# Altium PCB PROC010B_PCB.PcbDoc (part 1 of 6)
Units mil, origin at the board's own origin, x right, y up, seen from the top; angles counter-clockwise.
Board outline 3180 x 2565 mil, 6 copper layers (TOP, L2, L3, L4, L5, BOTTOM), stack 55.54 mil thick; 362 components, 264 nets, 1248 pads, 1144 vias.
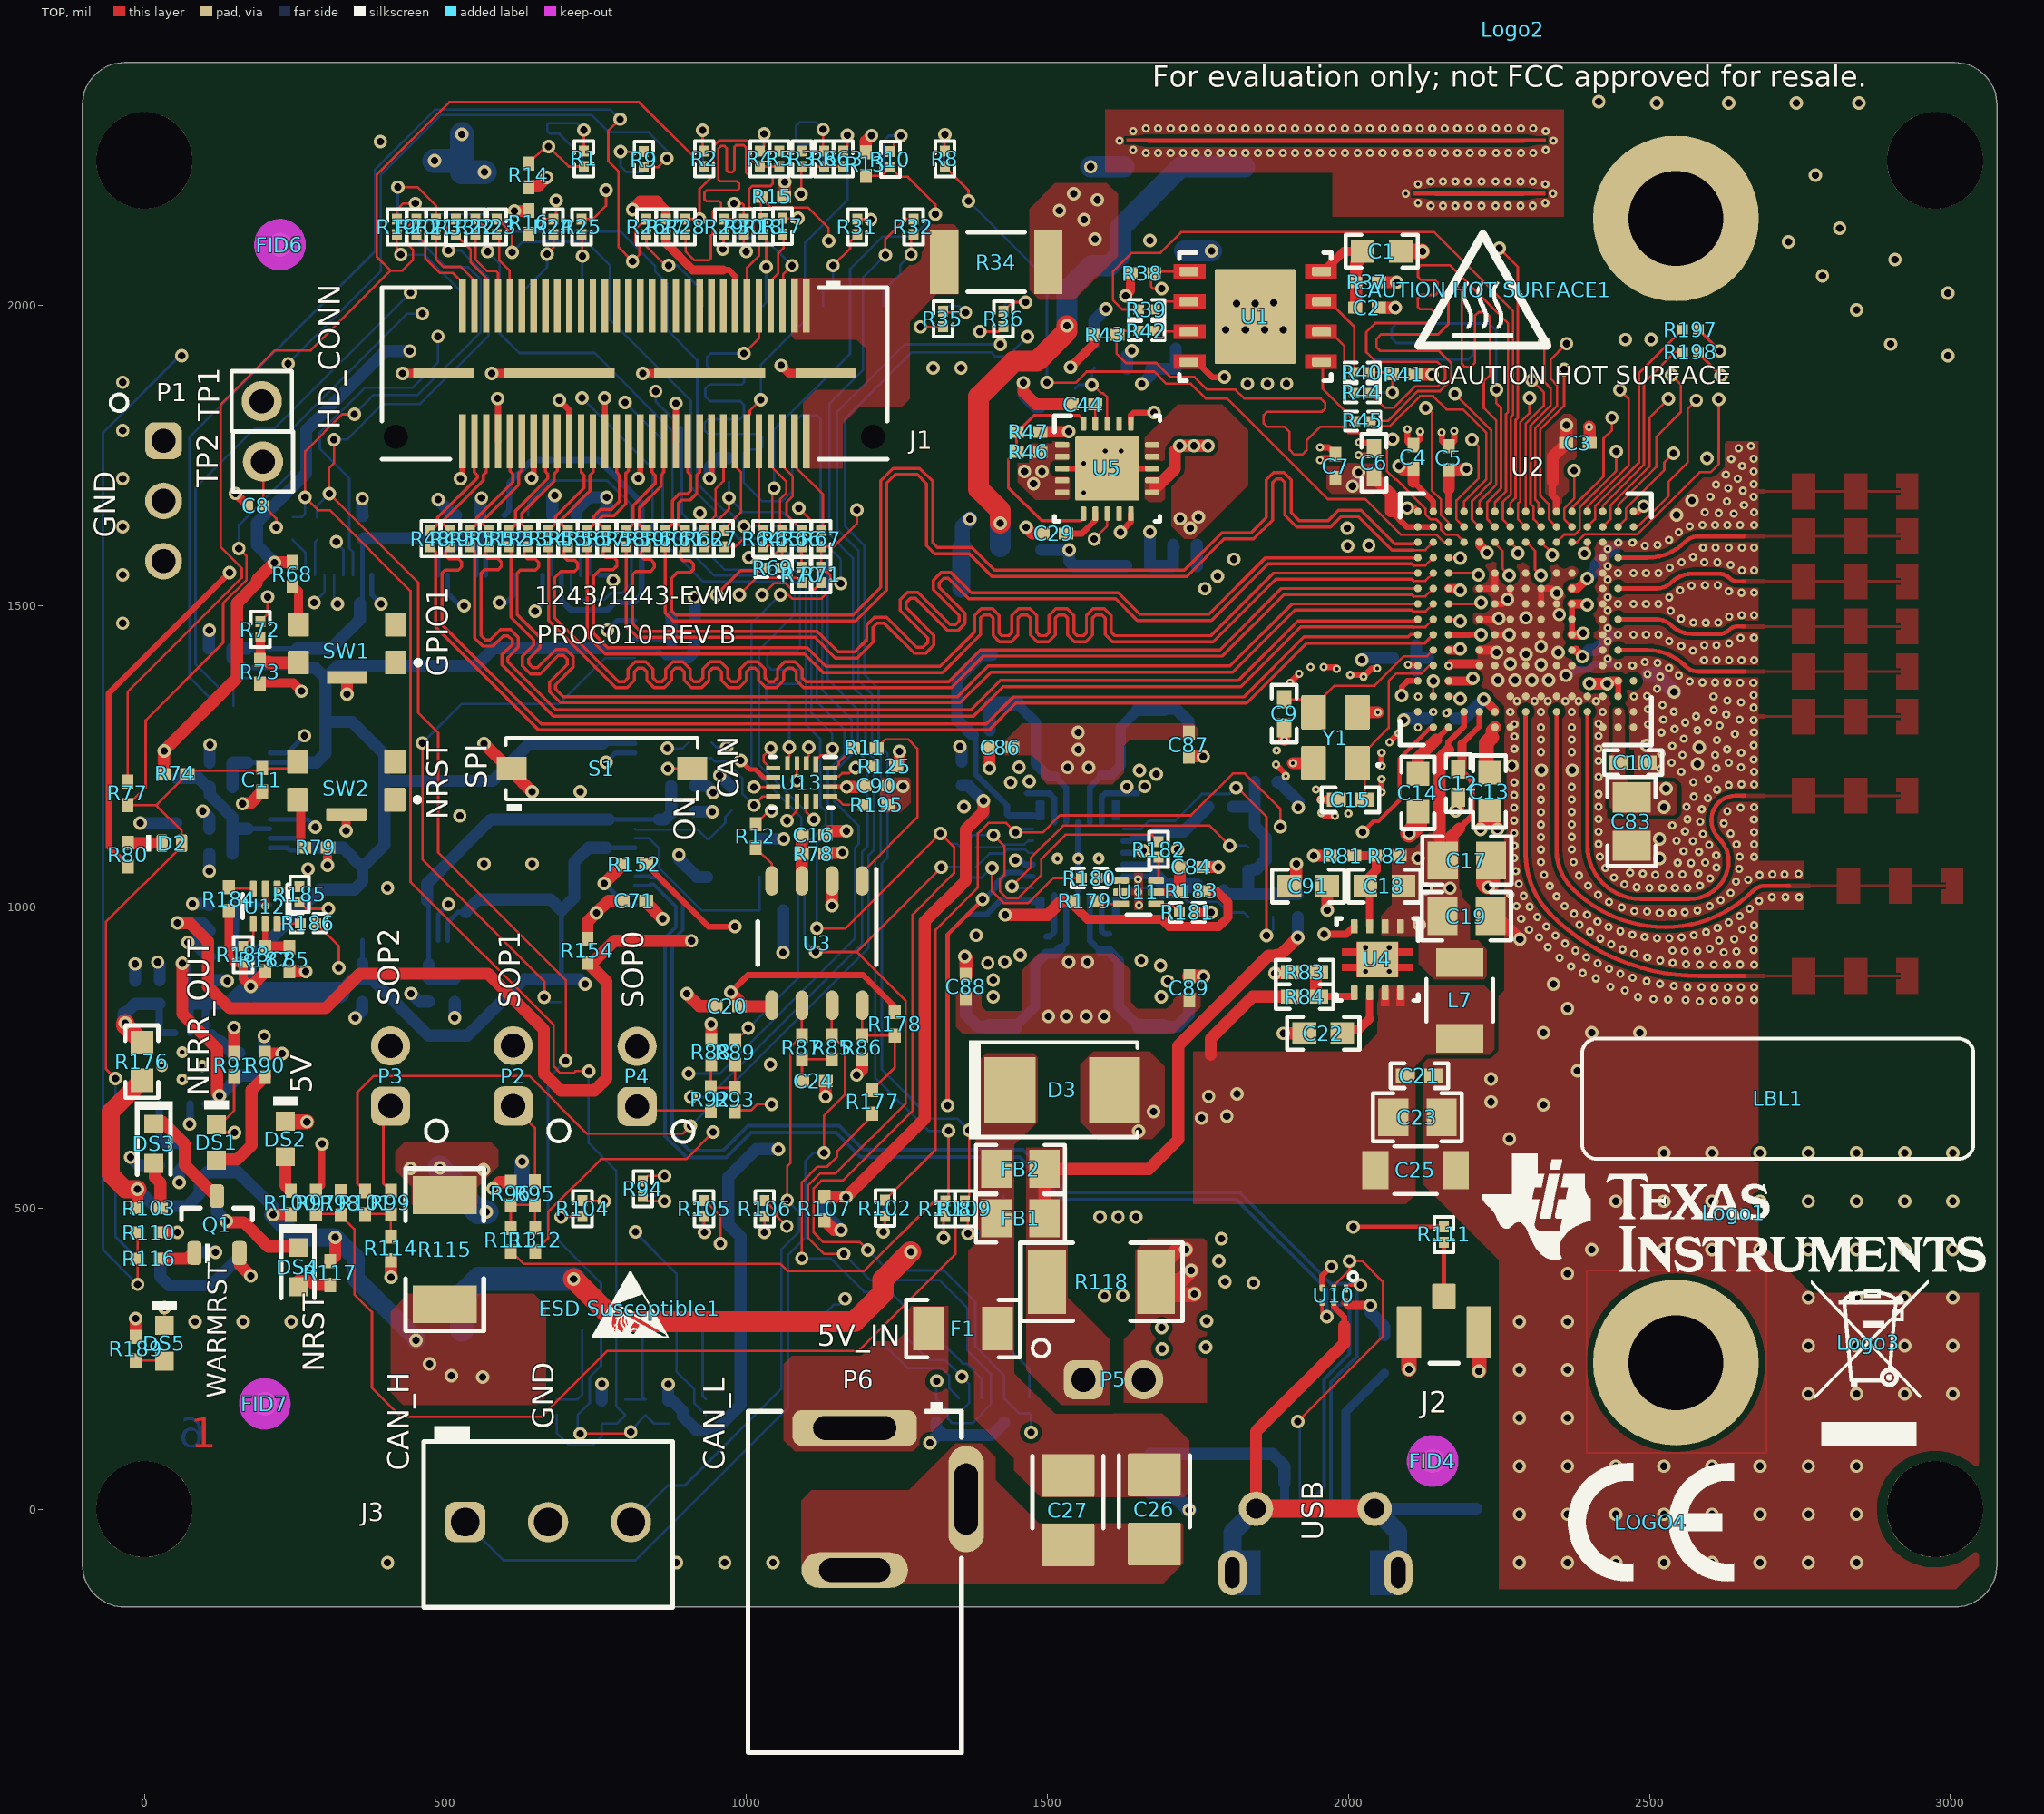
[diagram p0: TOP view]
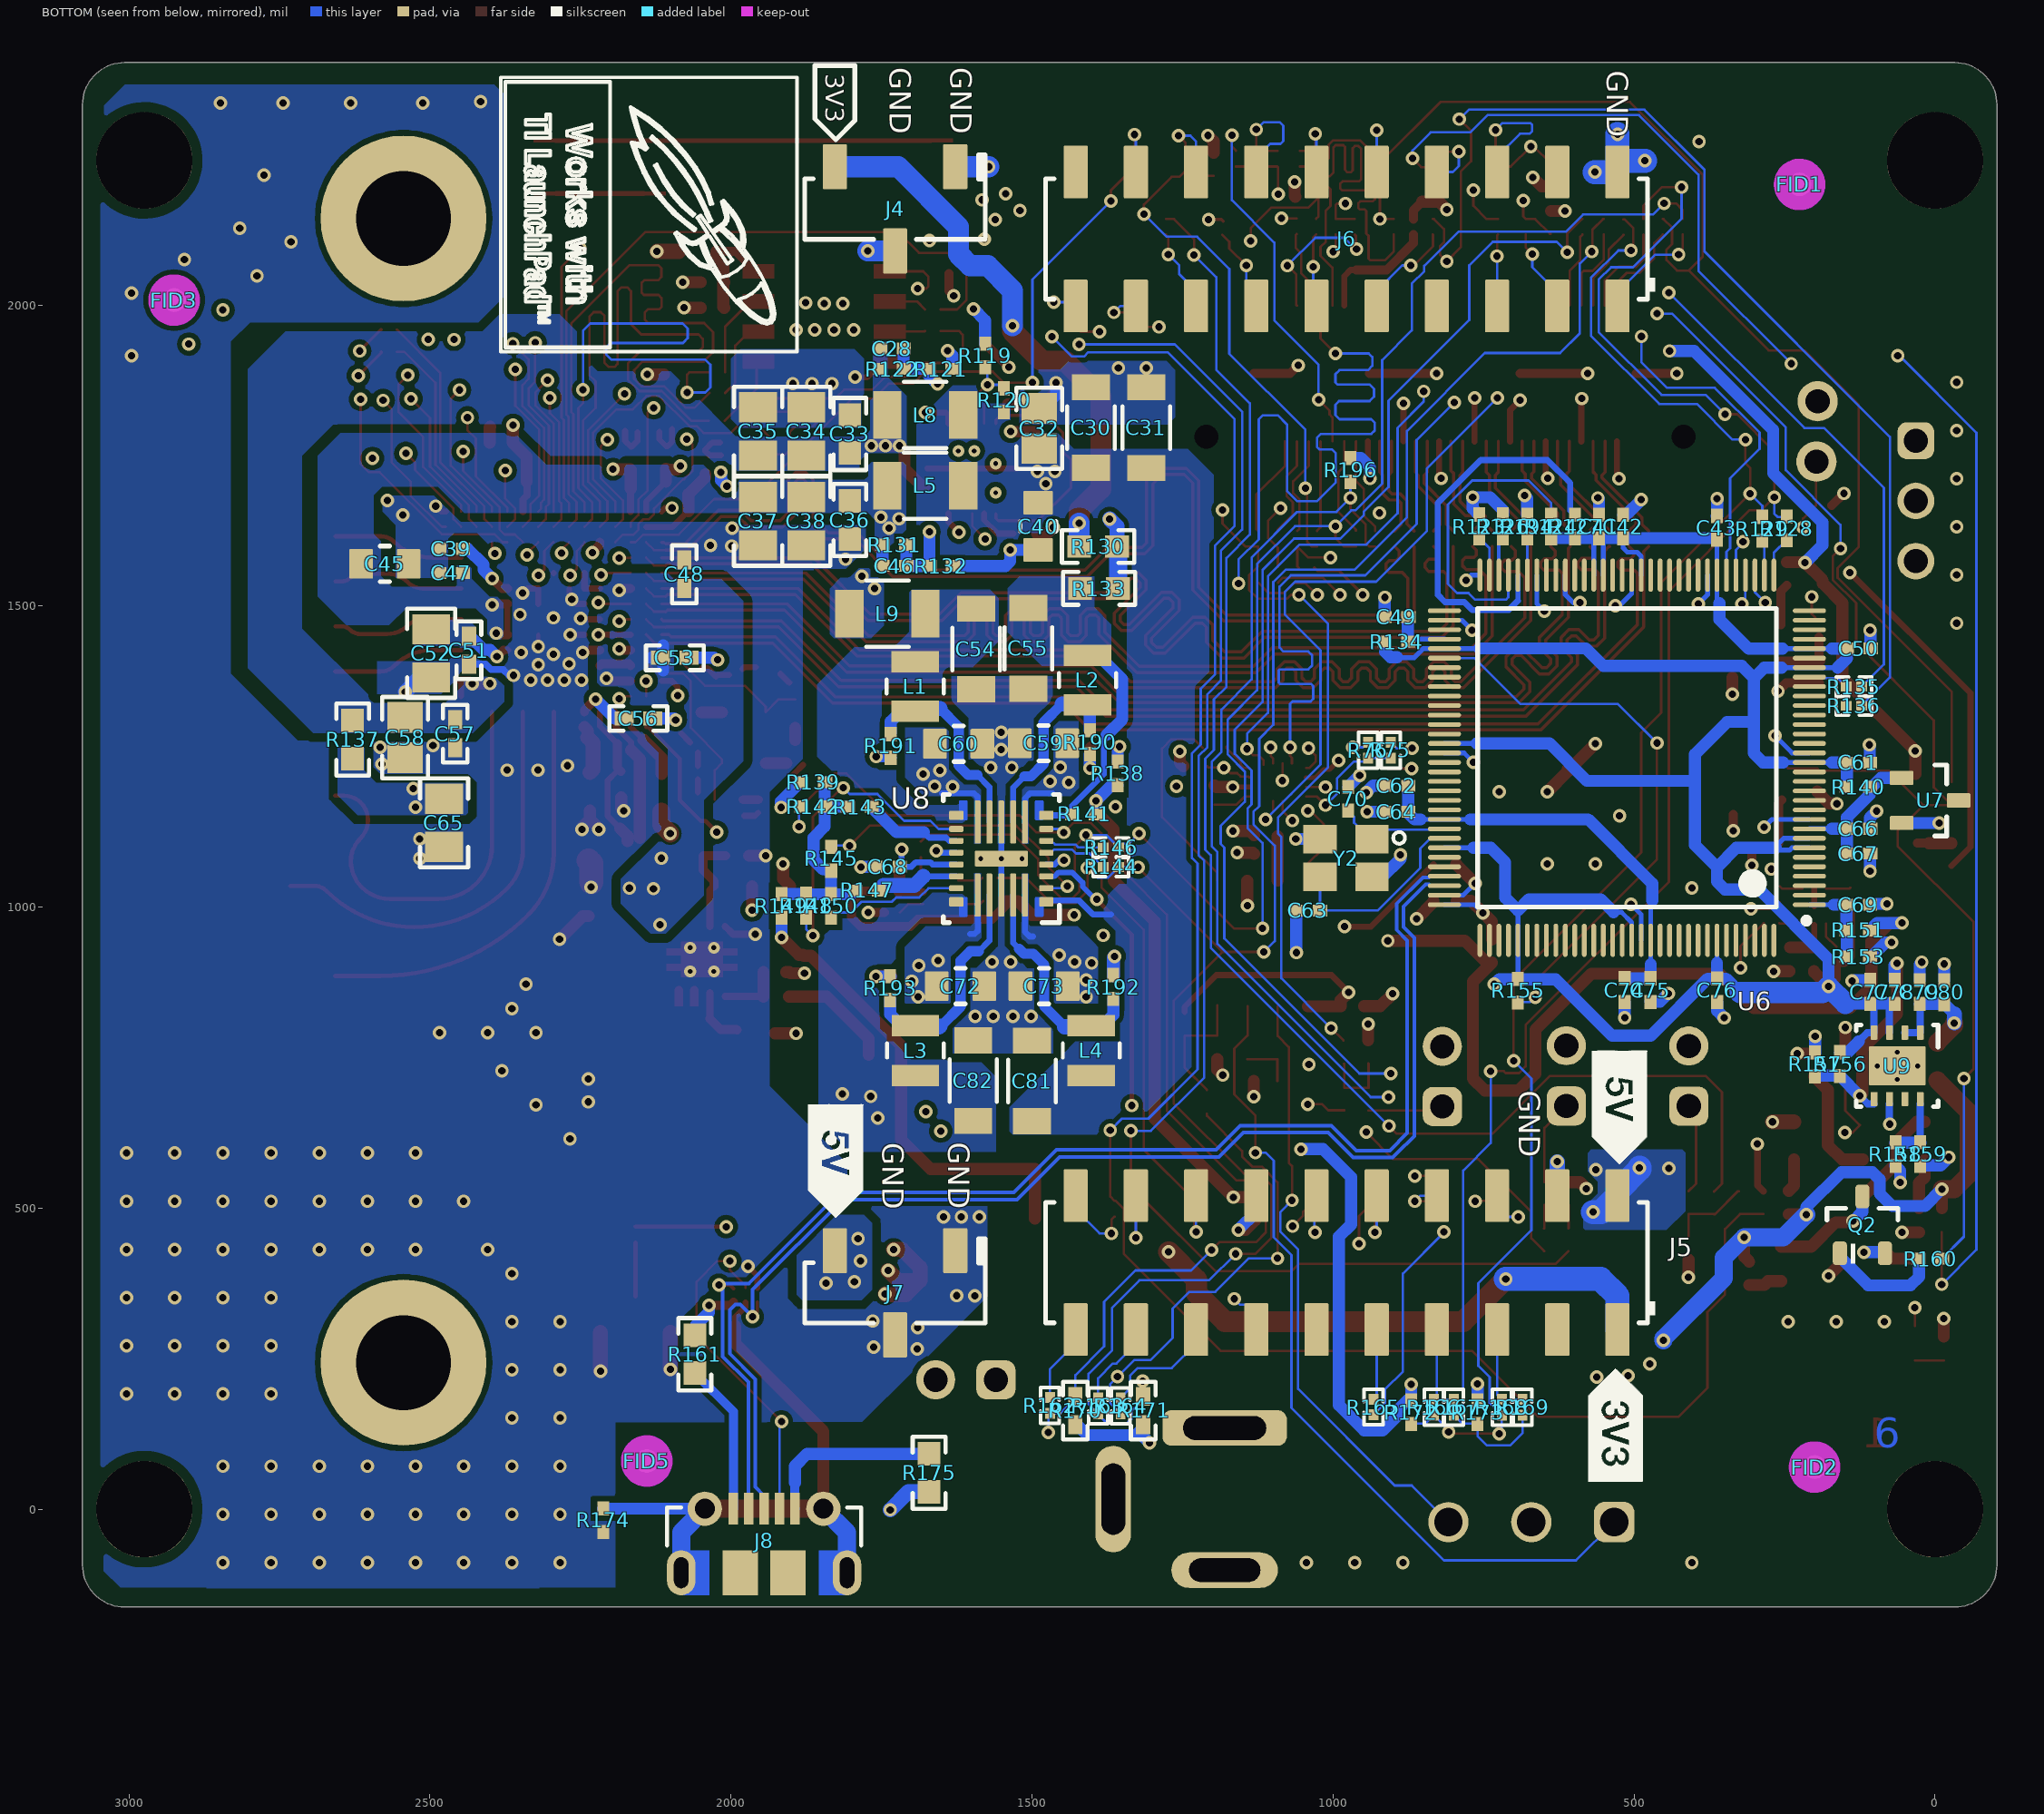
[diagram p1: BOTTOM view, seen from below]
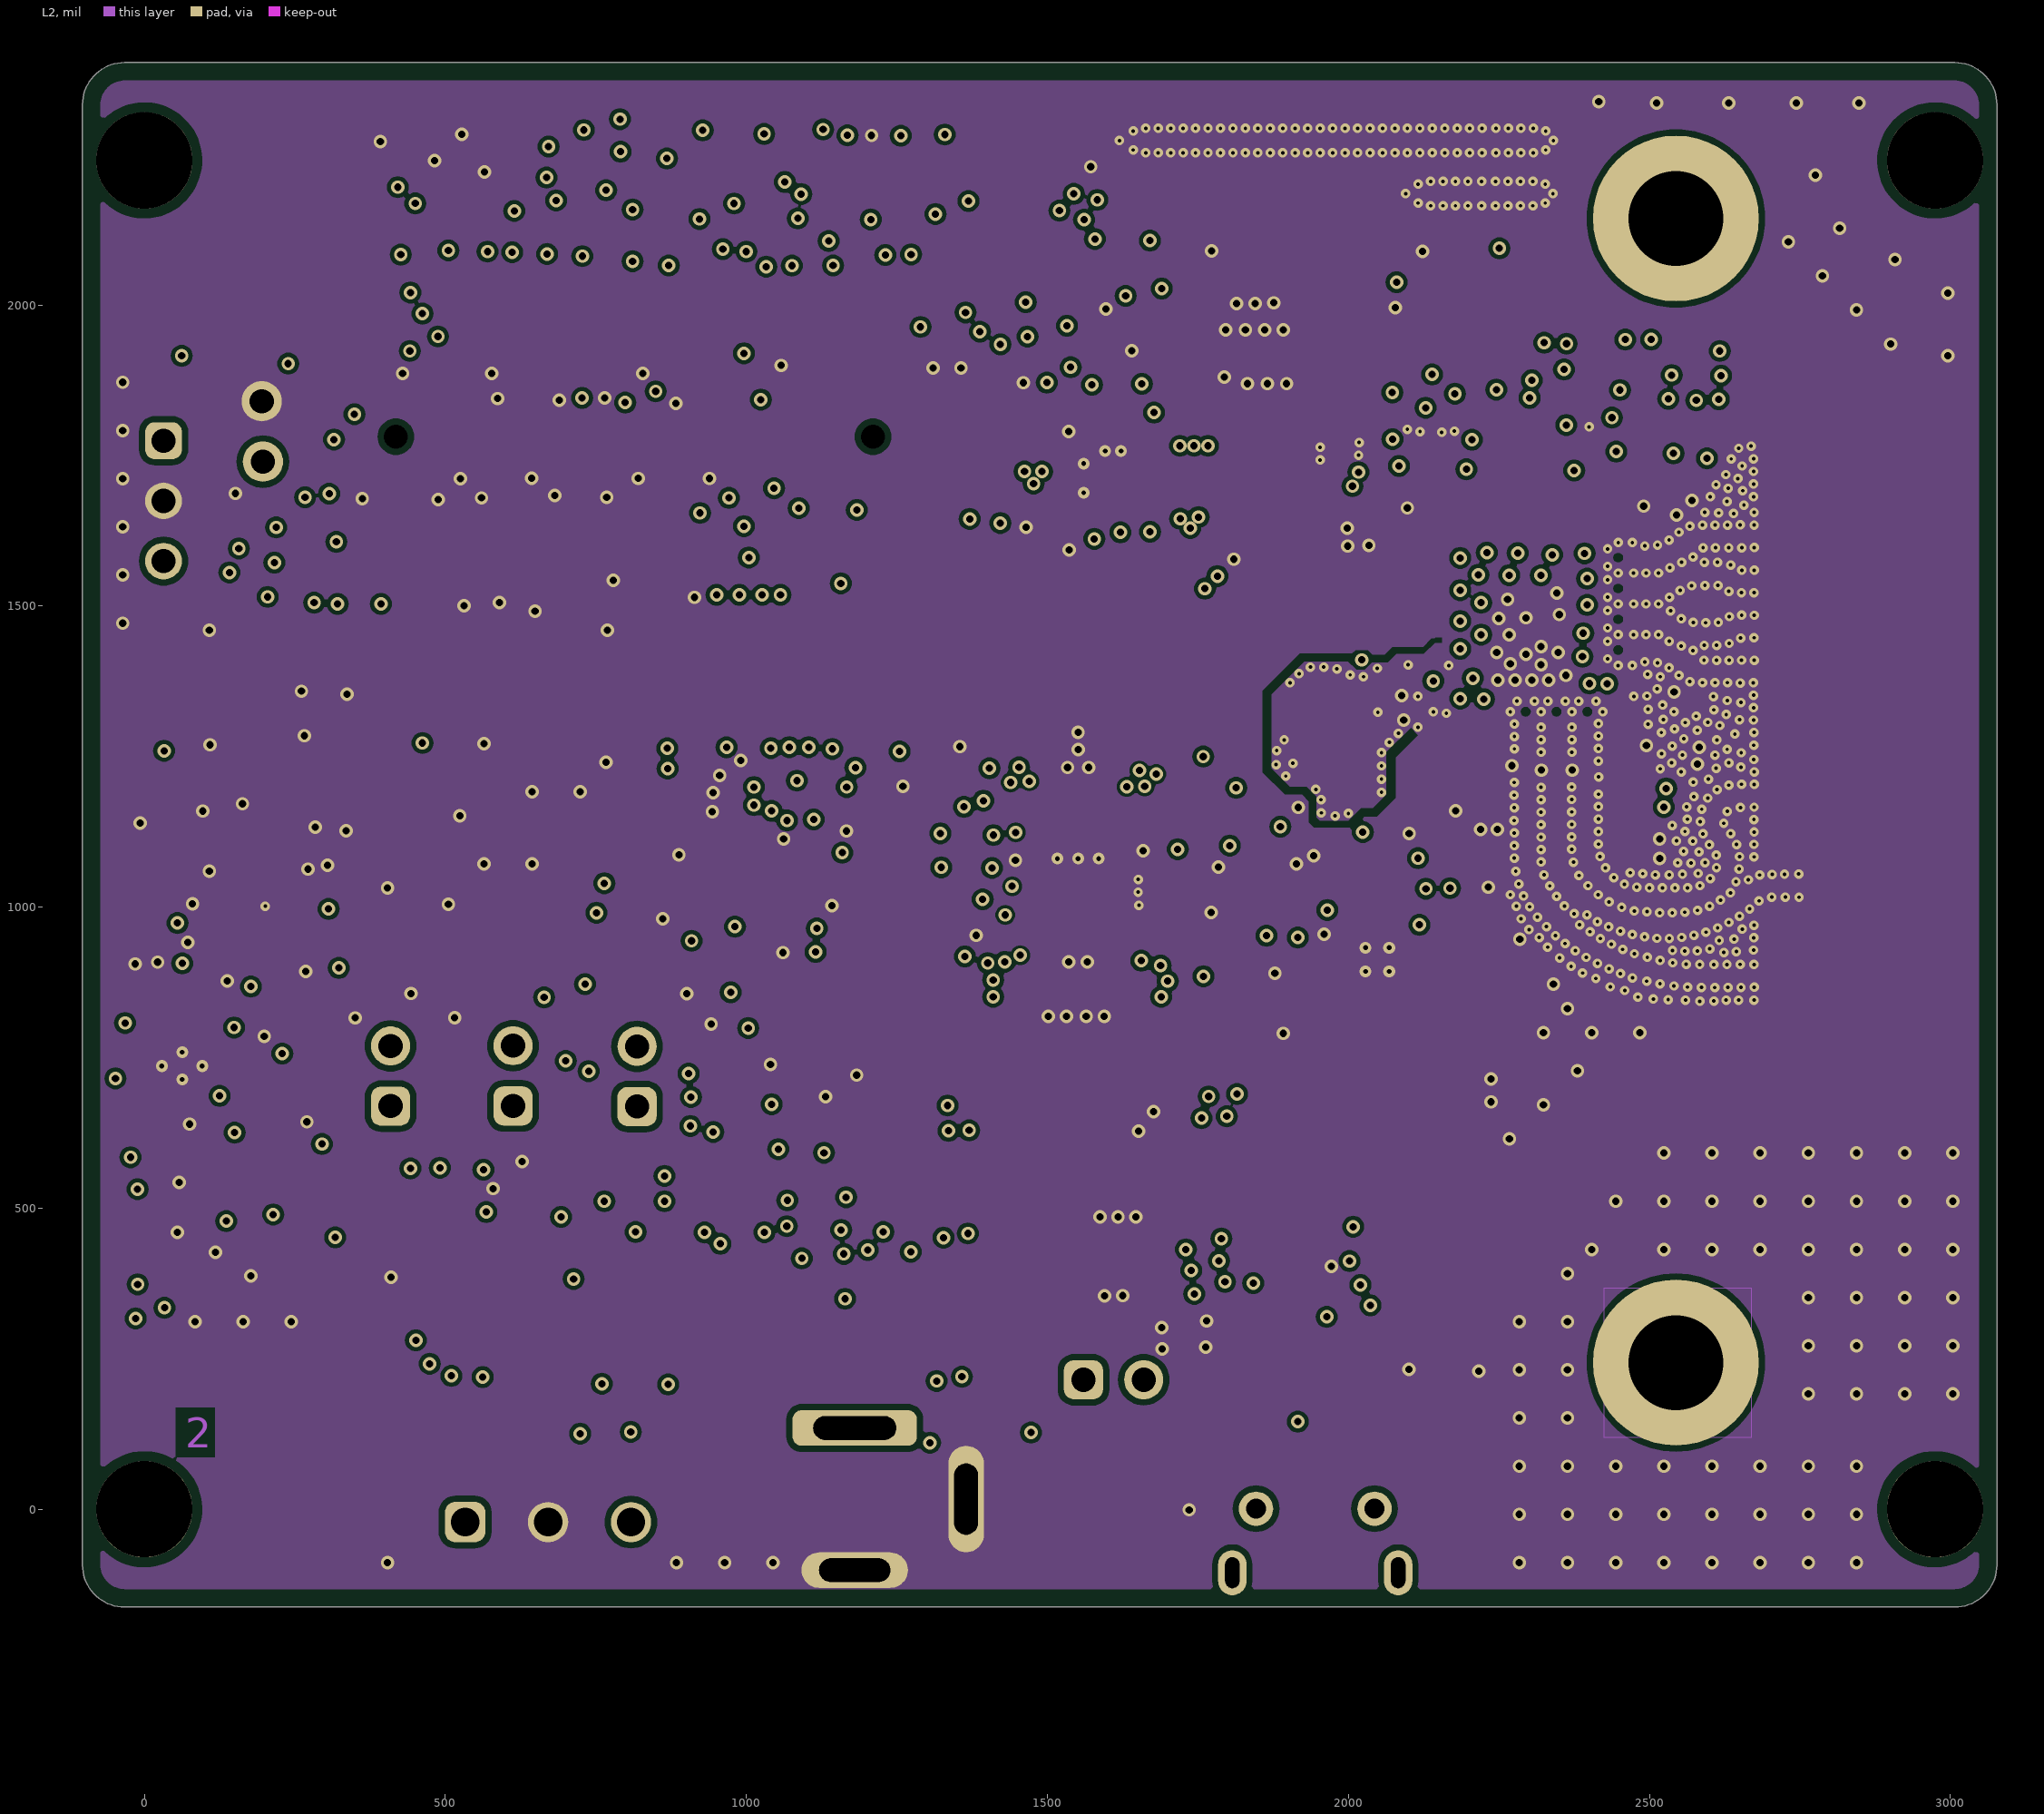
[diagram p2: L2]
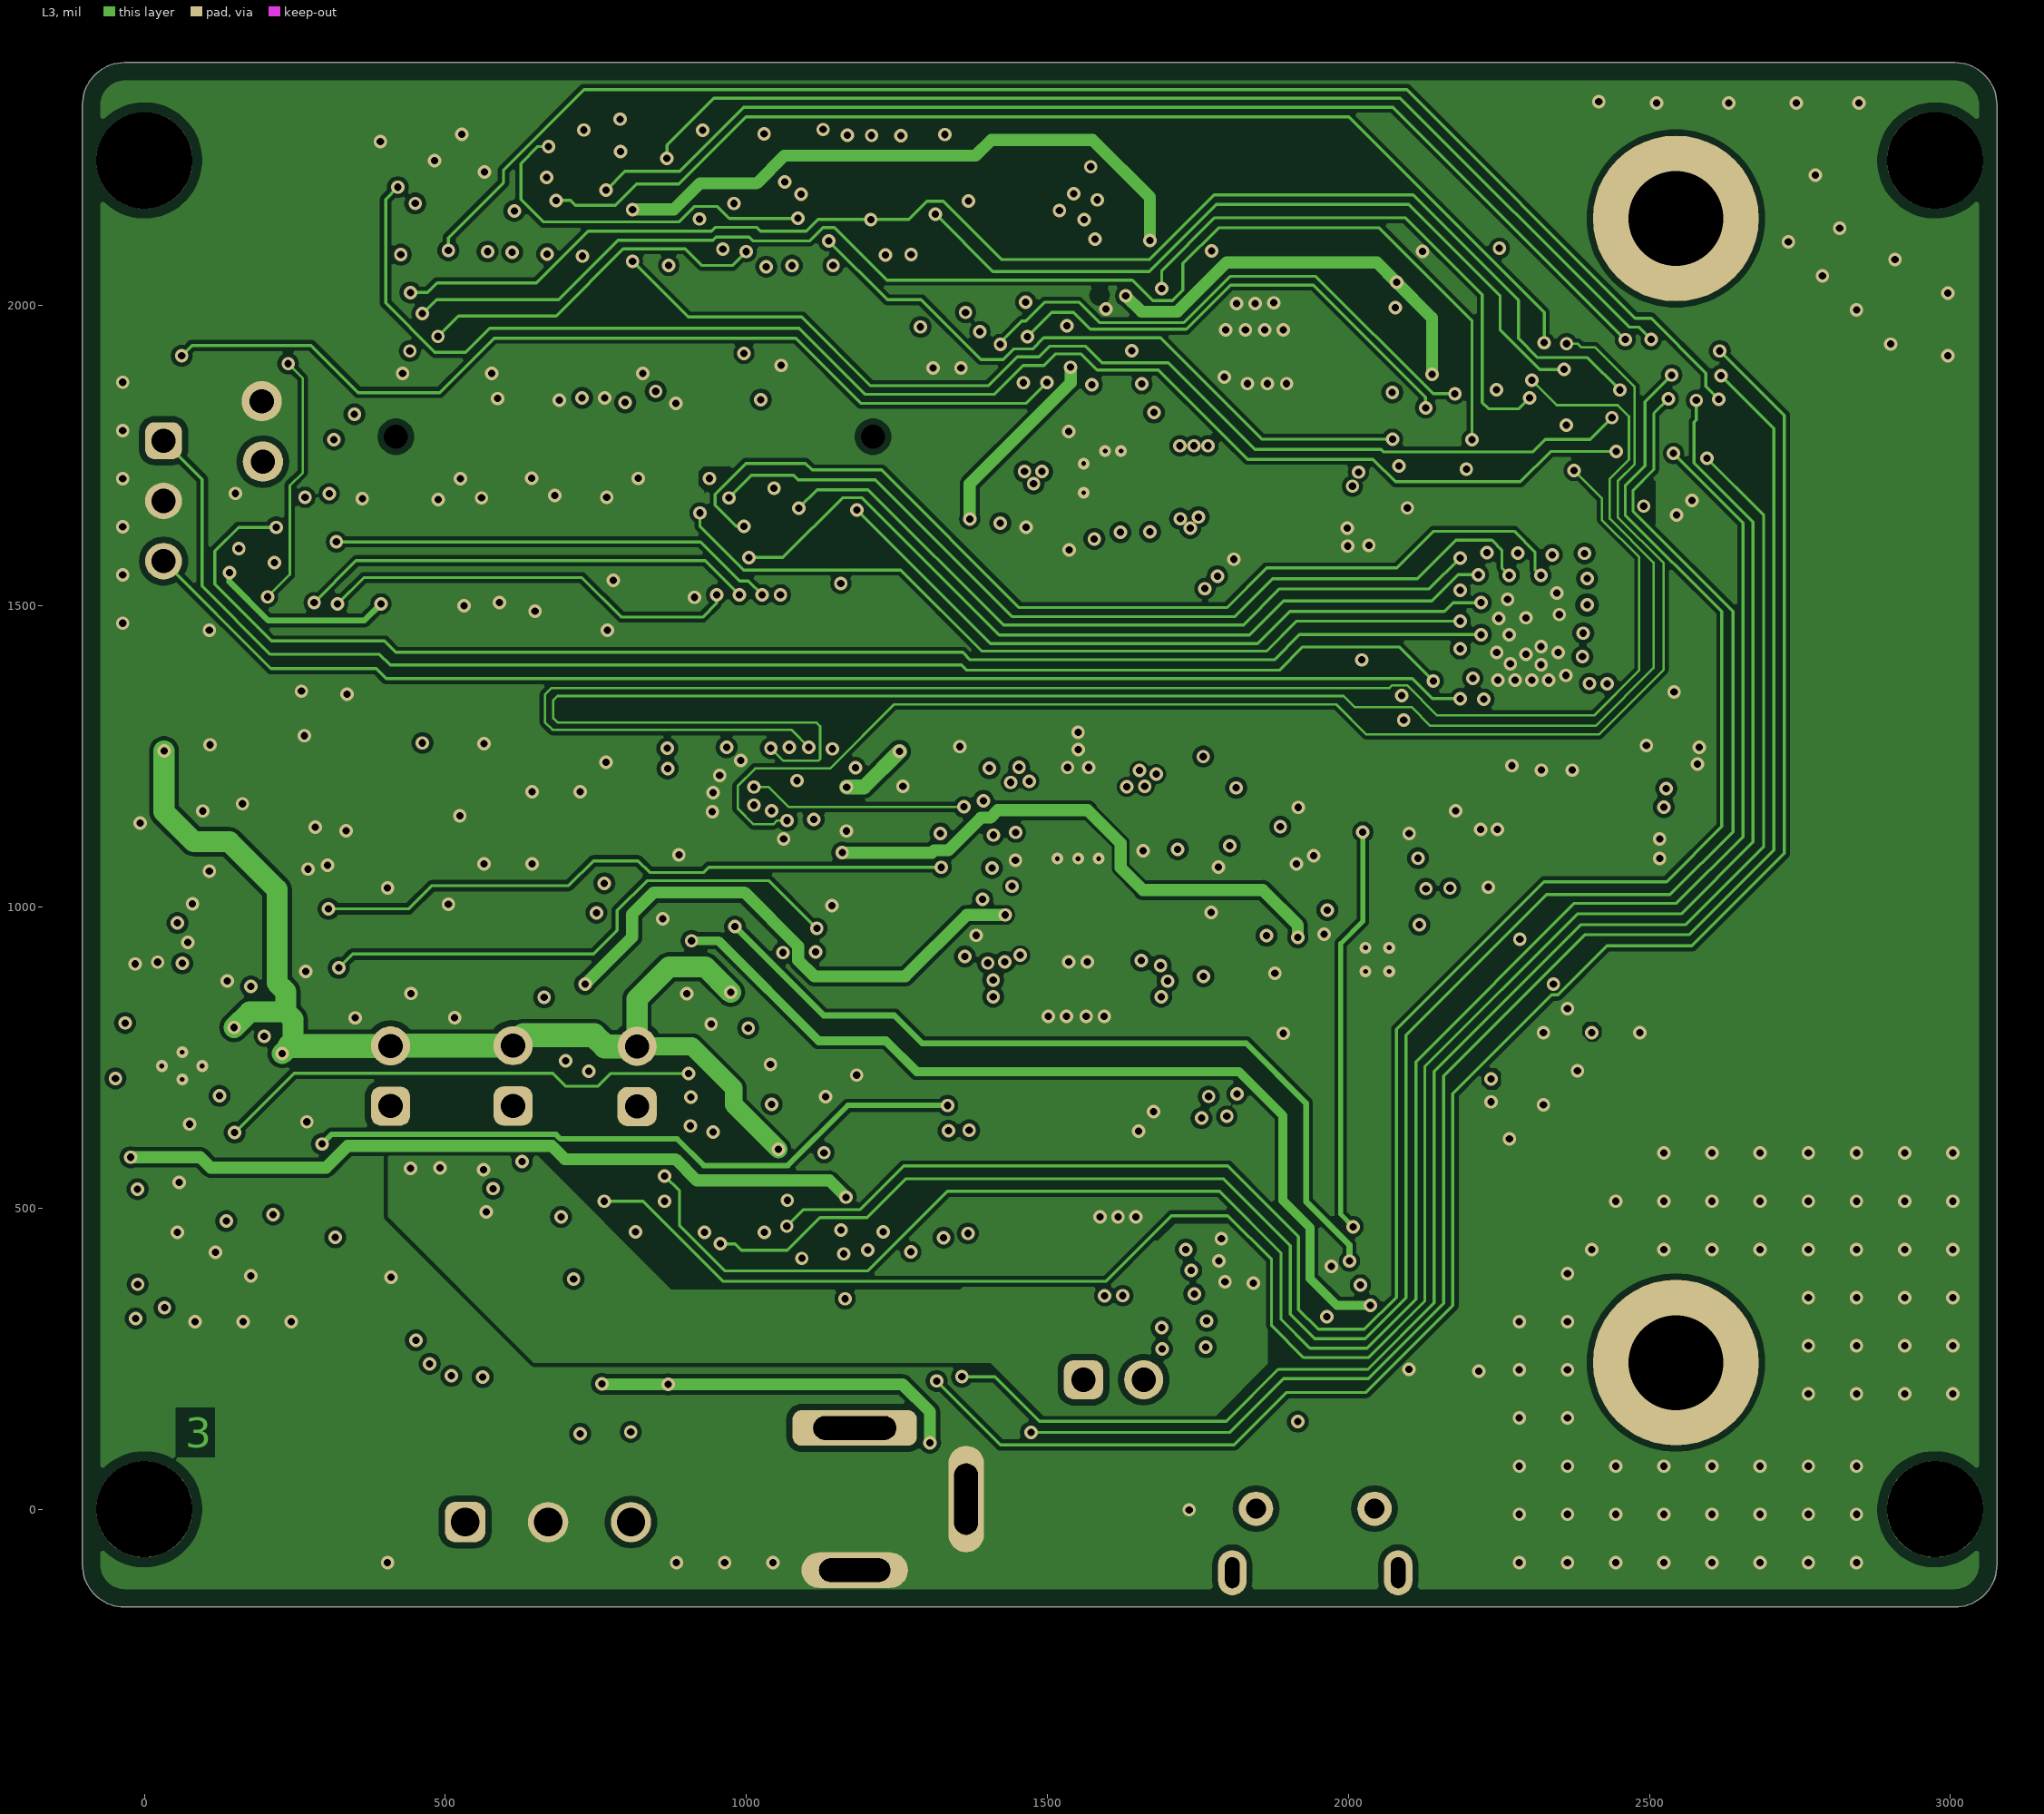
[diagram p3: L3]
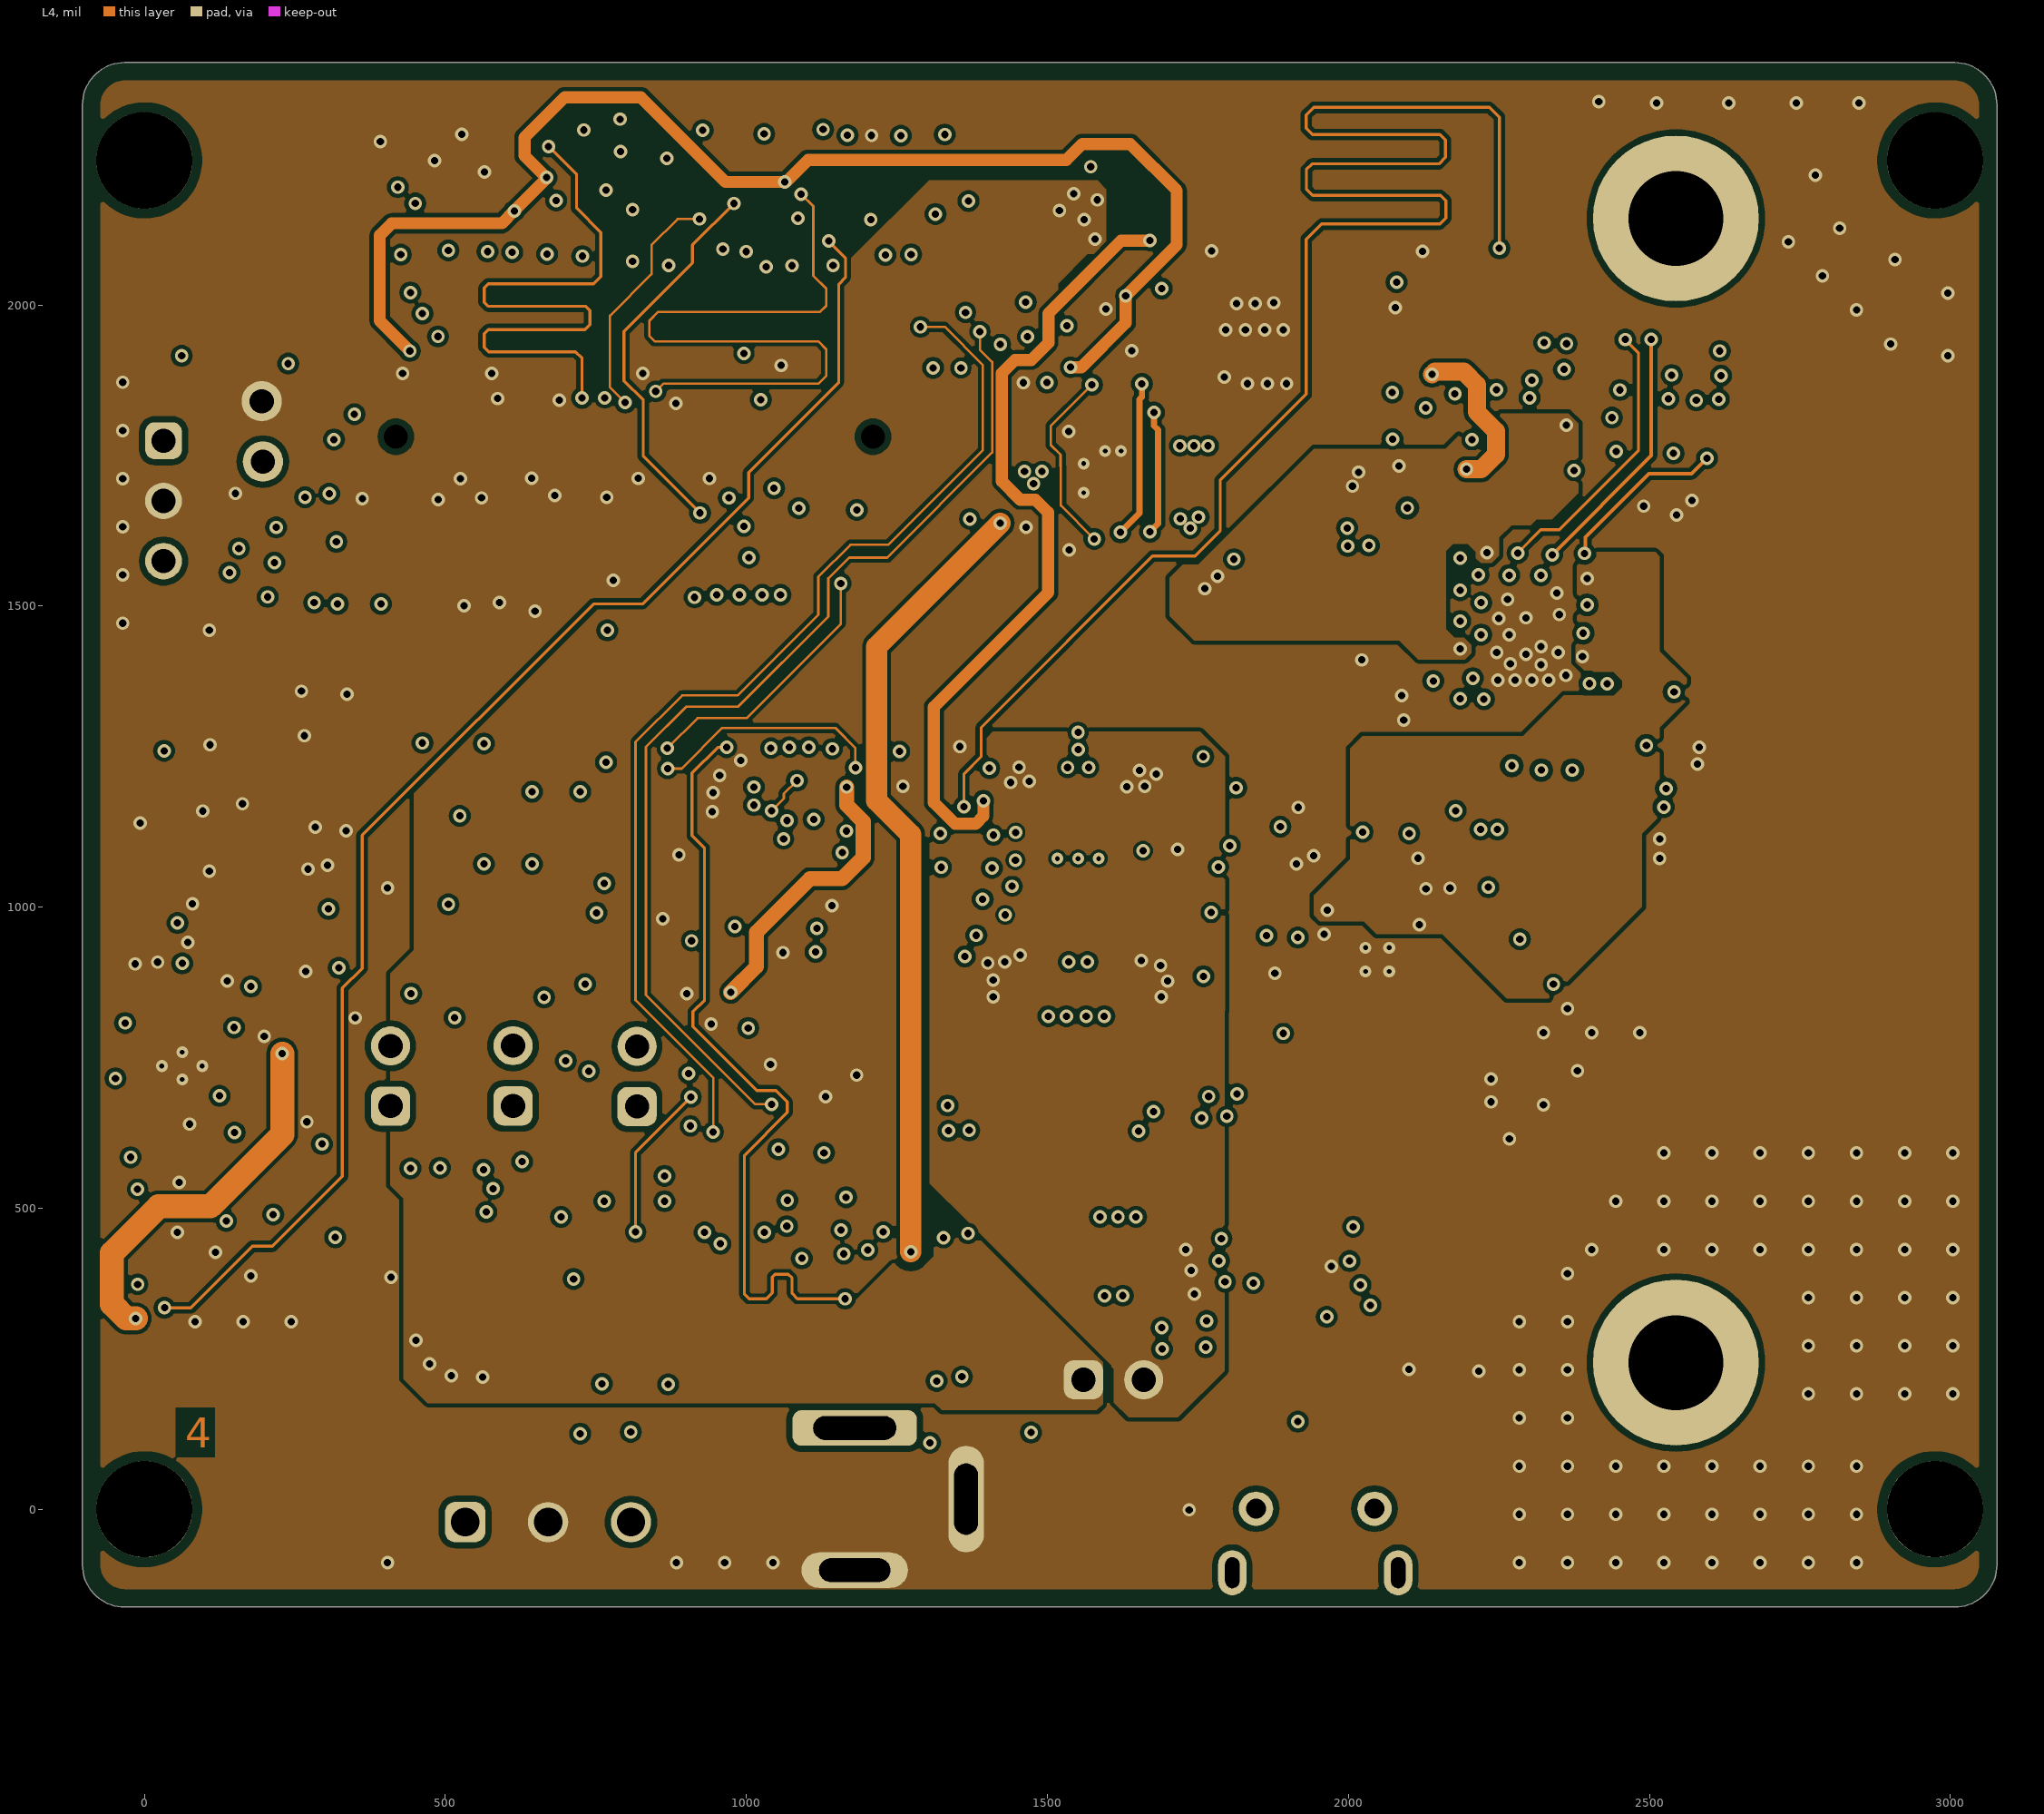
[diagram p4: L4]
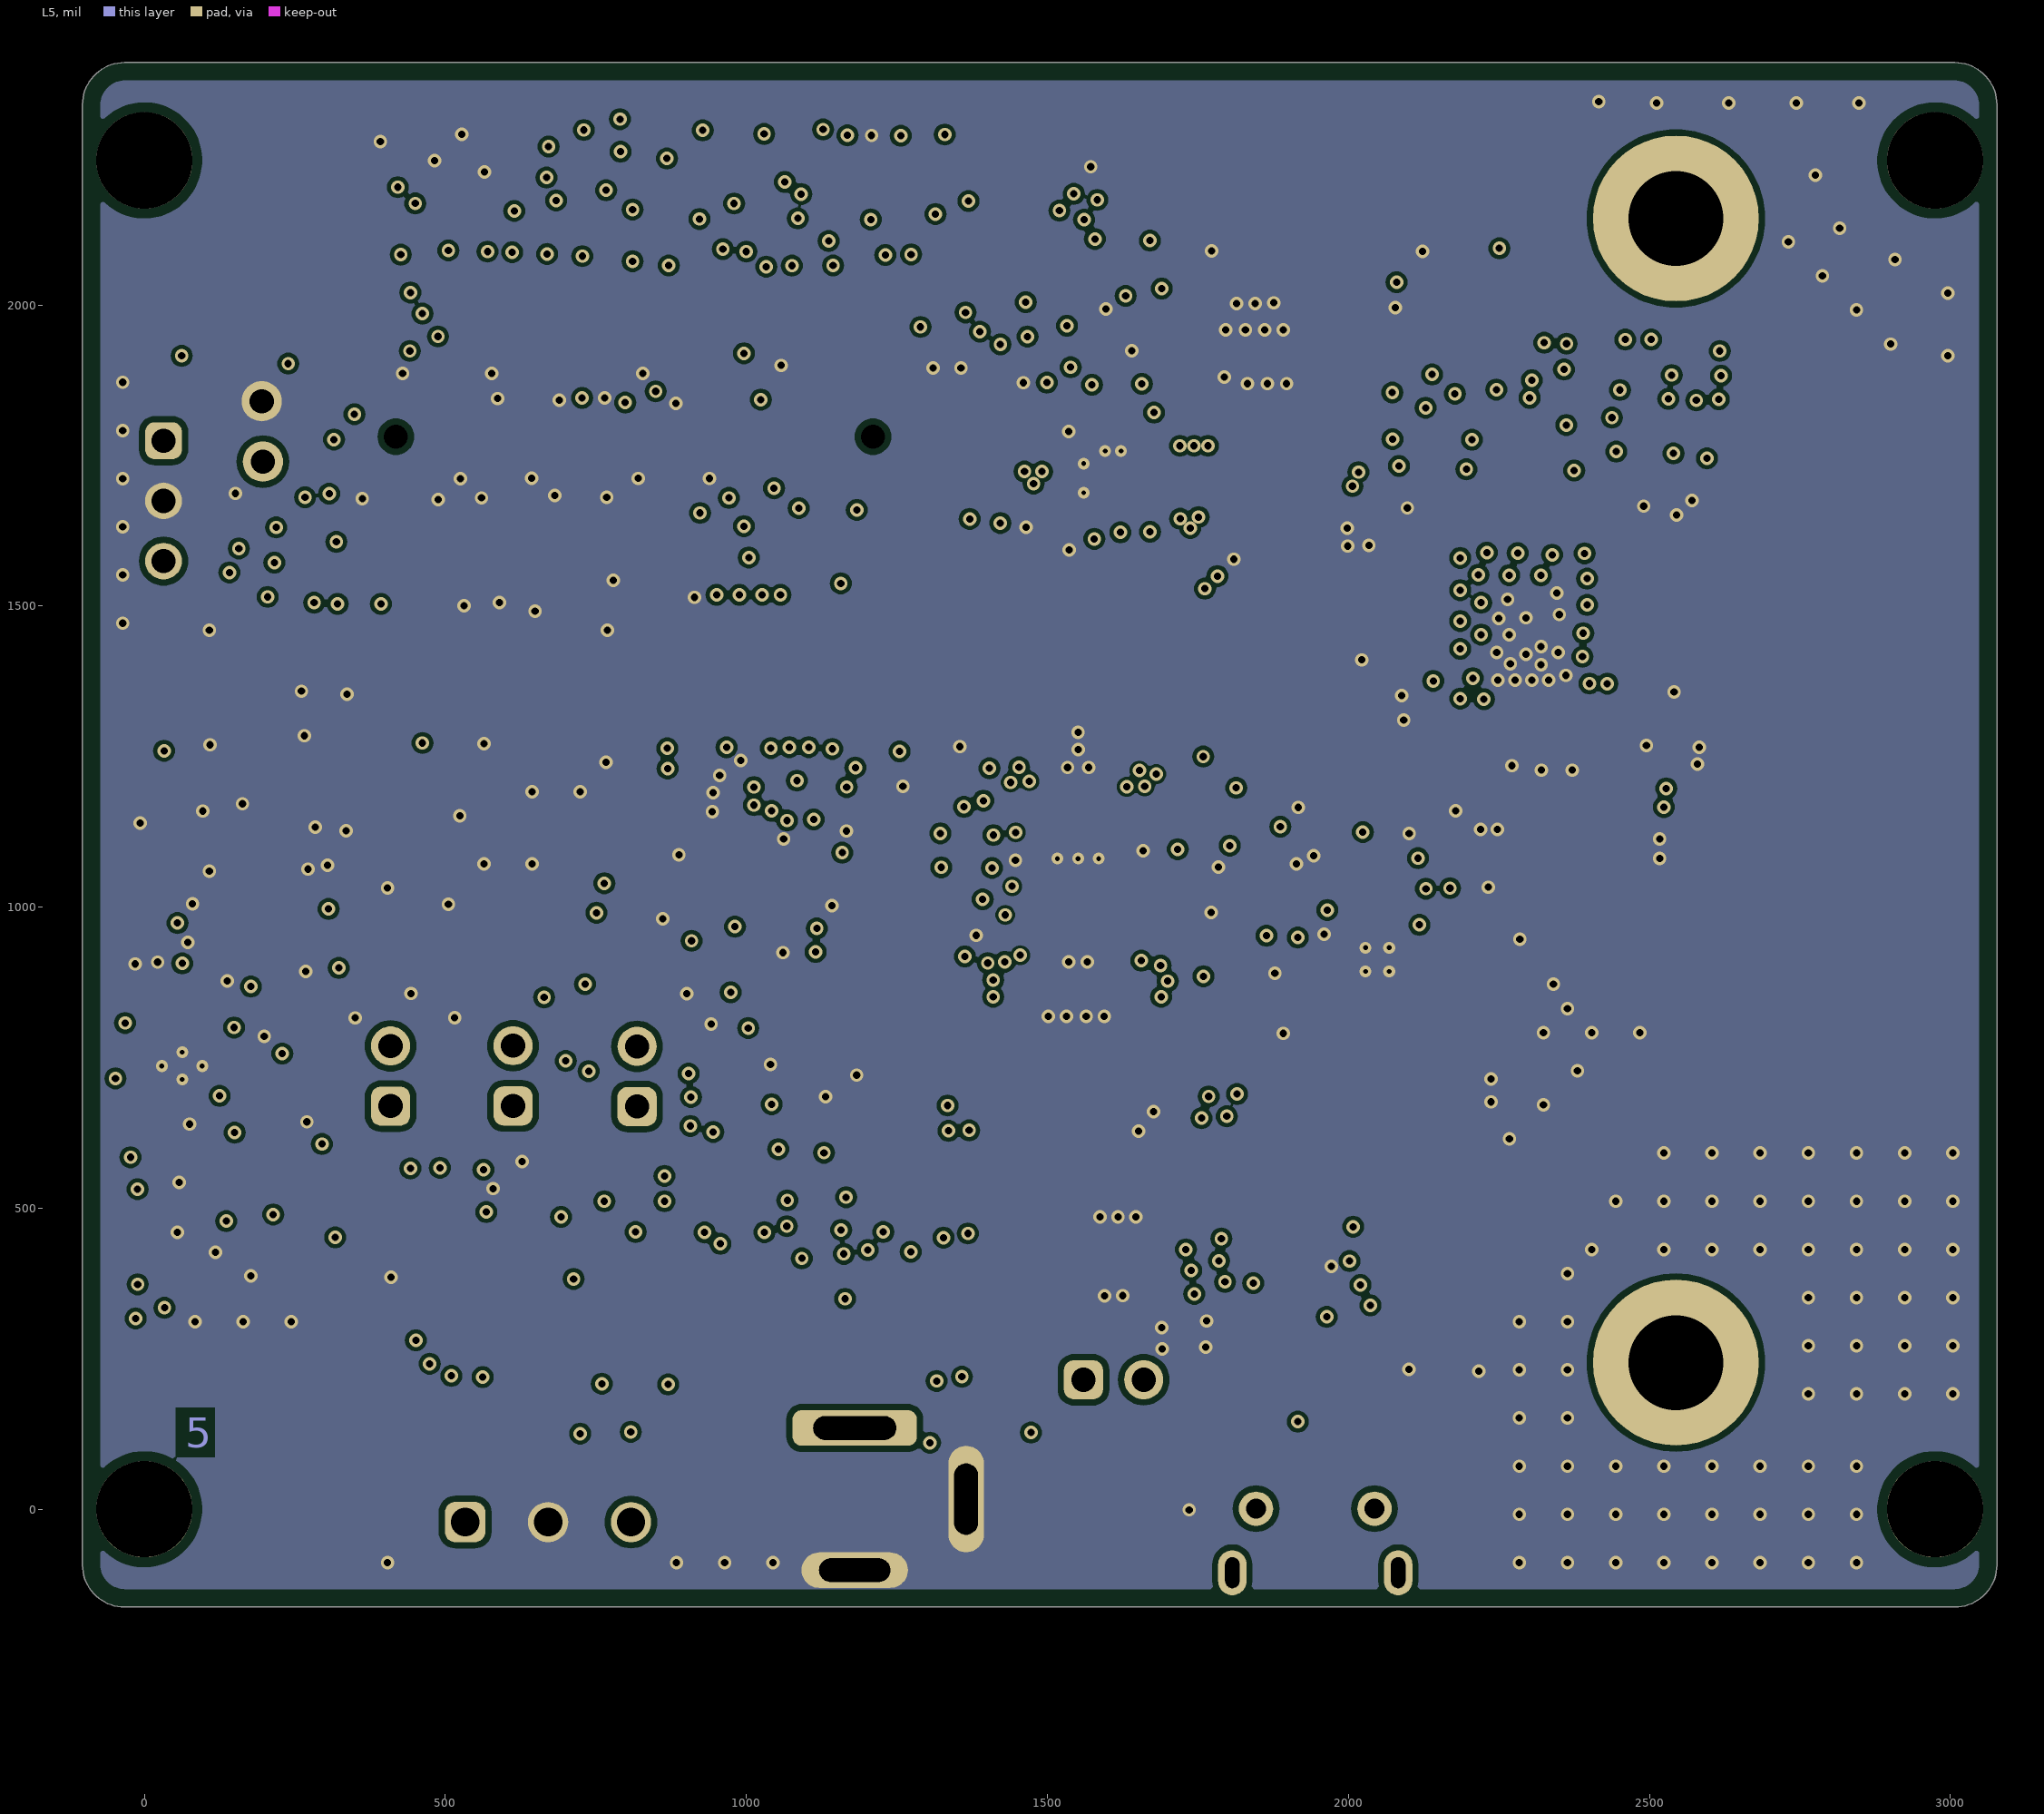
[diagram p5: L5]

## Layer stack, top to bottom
Top Solder: solder mask 0.8, Solder Resist, Dk 3.5
TOP: signal copper 1.6
Dielectric 1: core 4, RO4835 LOPRO, Dk 3.66
L2: signal copper 1.2
Dielectric2: core 2.85, FR4 370HR, Dk 3.9
Dielectric 3: dielectric 2.85, FR4 370HR, Dk 3.9
L3: signal copper 1.2
Dielectric4: core 28, FR4 370HR, Dk 4.36
L4: signal copper 1.2
Dielectric5: core 2.92, FR4 370HR, Dk 3.9
Dielectric 6: dielectric 2.92, FR4 370HR, Dk 3.9
L5: signal copper 1.2
Dielectric7: core 4, FR4 370HR, Dk 4.26
BOTTOM: signal copper 1.6
Bottom Solder: solder mask 0.8, Solder Resist, Dk 3.5

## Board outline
-32.75,-162.5 cw(c-32.75,-92.5) -102.75,-92.5 -102.75,2332.5 cw(c-32.75,2332.5) -32.75,2402.5 3007.25,2402.5 cw(c3007.25,2332.5) 3077.25,2332.5 3077.25,-92.5 cw(c3007.25,-92.5) 3007.25,-162.5

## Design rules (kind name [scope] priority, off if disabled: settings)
Clearance Clearance_RF [InNetClass('RF') and not ispad vs inpoly] p1: gap=6.73 ignorepadtopadclearanceinfootprint=FALSE
Clearance Clearance_L34 [InLayerClass('L3_L4')] p2: gap=15 ignorepadtopadclearanceinfootprint=FALSE except(0: Arc-Hole Track-Hole SMDPad-Hole THPad-Hole Via-Hole Fill-Hole Poly-Hole Region-Hole Text-Hole; 5: Arc-Track Arc-SMDPad Track-Track Track-SMDPad; 5.9: Via-Via; 6: Arc-Arc Arc-THPad Arc-Via Track-THPad Track-Via SMDPad-SMDPad SMDPad-THPad SMDPad-Via SMDPad-Fill SMDPad-Poly THPad-THPad THPad-Via Via-Fill Via-Poly; 10: THPad-Fill THPad-Poly)
Clearance Clearance_PMIC [WithinRoom('Copper to PMIC IC')] p3: gap=5 ignorepadtopadclearanceinfootprint=FALSE except(0: Arc-Hole Track-Hole SMDPad-Hole THPad-Hole Via-Hole Fill-Hole Poly-Hole Region-Hole Text-Hole; 4: Arc-Track Track-Track; 4.5: Track-Via SMDPad-SMDPad)
Clearance Clearance_BTM [OnLayer('BOTTOM')] p4: gap=15 ignorepadtopadclearanceinfootprint=FALSE except(0: Arc-SMDPad Arc-Hole Track-Hole SMDPad-Hole THPad-Hole Via-Hole Fill-Hole Poly-Hole Region-Hole Text-Hole; 4: Track-SMDPad; 4.5: Arc-Via Track-Via; 5: Arc-Arc Arc-Track Track-Track SMDPad-Via; 6: Arc-THPad Track-THPad SMDPad-SMDPad SMDPad-THPad THPad-THPad THPad-Via; 8: Arc-Fill Arc-Poly Track-Fill Track-Poly Via-Fill Via-Poly; 9: SMDPad-Fill SMDPad-Poly THPad-Fill THPad-Poly; 16.6: Via-Via)
Clearance Clearance_L25 [InLayerClass('L2_L5')] p5: gap=15 ignorepadtopadclearanceinfootprint=FALSE except(0: Arc-Hole Track-Hole SMDPad-Hole THPad-Hole Via-Hole Fill-Hole Poly-Hole Region-Hole Text-Hole; 5: Arc-Track Arc-SMDPad Track-Track Track-SMDPad; 6: Arc-Arc Arc-THPad Arc-Via Track-THPad Track-Via SMDPad-SMDPad SMDPad-THPad SMDPad-Via SMDPad-Fill SMDPad-Poly THPad-THPad THPad-Via Via-Via Via-Fill Via-Poly; 10: THPad-Fill THPad-Poly)
Clearance RX_TX_L34 [InLayerClass('L3_L4') vs InNetClass('RX_TX')] p6: gap=10 ignorepadtopadclearanceinfootprint=FALSE except(0: Arc-Hole Track-Hole SMDPad-Hole THPad-Hole Via-Hole Fill-Hole Poly-Hole Region-Hole Text-Hole; 4.86: Via-Via; 5: Arc-SMDPad Track-SMDPad; 6: Arc-Arc Arc-Track Arc-THPad Arc-Via Track-Track Track-THPad Track-Via SMDPad-SMDPad SMDPad-THPad SMDPad-Via SMDPad-Fill SMDPad-Poly THPad-THPad THPad-Via Via-Fill Via-Poly; 15: Arc-Fill Arc-Poly Track-Poly Fill-Fill Fill-Poly Poly-Poly; 16: Track-Fill)
Clearance COPLANNER [WithinRoom('COUPLE') and not OnLayer('L4')] p7: gap=3 ignorepadtopadclearanceinfootprint=FALSE except(0: Arc-Hole Track-Hole SMDPad-Hole THPad-Hole Via-Hole Fill-Hole Poly-Hole Region-Hole Text-Hole)
Clearance Clearance_1 [WithinRoom('DUT') OR InPolygon] p8: gap=6.71 ignorepadtopadclearanceinfootprint=FALSE except(0: Arc-Hole Track-Hole SMDPad-Hole THPad-Hole Via-Hole Fill-Hole Poly-Hole Region-Hole Text-Hole; 4: Track-Track Track-SMDPad Track-Via SMDPad-Via; 6.6: Via-Region; 6.72: Arc-Region Arc-Text Track-Region Track-Text SMDPad-Region SMDPad-Text THPad-Region THPad-Text Via-Text Fill-Region Fill-Text Poly-Region Poly-Text Region-Region Region-Text Text-Text; 9: SMDPad-Poly; 10: THPad-Poly)
Clearance Clearance_TOP [OnLayer('TOP')] p9: gap=10 ignorepadtopadclearanceinfootprint=FALSE except(0: Arc-SMDPad Arc-Hole Track-Hole SMDPad-Hole THPad-Hole Via-Hole Fill-Hole Poly-Hole Region-Hole Text-Hole; 4: Arc-Arc Arc-Track Arc-Via Track-Track Track-Via; 5: Track-SMDPad SMDPad-Via; 6: Arc-THPad Track-THPad SMDPad-SMDPad SMDPad-THPad THPad-THPad THPad-Via Via-Fill Via-Poly; 8: Arc-Fill Arc-Poly Track-Fill Track-Poly; 9: SMDPad-Fill SMDPad-Poly THPad-Fill THPad-Poly; 15: Fill-Fill Fill-Poly Poly-Poly; 15.4: Via-Via)
Clearance RX_TX_L25 [InLayerClass('L2_L5') vs InNetClass('RX_TX')] p10: gap=10 ignorepadtopadclearanceinfootprint=FALSE except(0: Arc-Hole Track-Hole SMDPad-Hole THPad-Hole Via-Hole Fill-Hole Poly-Hole Region-Hole Text-Hole; 5: Arc-SMDPad Track-SMDPad; 6: Arc-Arc Arc-Track Arc-THPad Arc-Via Track-Track Track-THPad Track-Via SMDPad-SMDPad SMDPad-THPad SMDPad-Via SMDPad-Fill SMDPad-Poly THPad-THPad THPad-Via Via-Fill Via-Poly; 9.1: Via-Via; 15: Arc-Fill Arc-Poly Track-Fill Track-Poly Fill-Fill Fill-Poly Poly-Poly)
Clearance RX_TX_TOP [OnLayer('TOP') vs InNetClass('RX_TX')] p11: gap=10 ignorepadtopadclearanceinfootprint=FALSE except(0: Arc-Hole Track-Hole SMDPad-Hole THPad-Hole Via-Hole Fill-Hole Poly-Hole Region-Hole Text-Hole; 4: Arc-Track Arc-SMDPad Track-Track Track-SMDPad SMDPad-Via; 6: Arc-THPad Track-THPad SMDPad-SMDPad SMDPad-THPad THPad-THPad THPad-Via THPad-Fill THPad-Poly; 6.7: Arc-Fill Arc-Poly Track-Fill Track-Poly; 6.72: Arc-Via Track-Via Via-Fill Via-Poly; 9: SMDPad-Fill SMDPad-Poly; 15.4: Via-Via)
Clearance same_net_cl_inner [InLayerClass('layers')] p12: gap=10 ignorepadtopadclearanceinfootprint=FALSE except(0: Arc-Hole Track-Hole SMDPad-Hole THPad-Hole Via-Hole Fill-Hole Poly-Hole Region-Hole Text-Hole; 5: Arc-THPad Track-Track Track-SMDPad Track-THPad SMDPad-SMDPad SMDPad-THPad THPad-THPad; 6: Track-Via SMDPad-Via THPad-Via Via-Via Via-Fill Via-Poly; 15: Arc-Fill Arc-Poly Fill-Fill Fill-Poly Poly-Poly)
ComponentClearance [All] p1: gap=-1 collisioncheckmode=3 verticalgap=2 showdistances=FALSE
DiffPairsRouting DiffPairsRouting_USB [InNetClass('USB')] p1: maxlimit=5.6 minlimit=5.6 mostfreqgap=5.6 toplayer_minwidth=6 toplayer_maxwidth=6 toplayer_prefwidth=6 midlayer1_minwidth=6 midlayer1_maxwidth=6 midlayer1_prefwidth=6 midlayer2_minwidth=6 midlayer2_maxwidth=6 midlayer2_prefwidth=6 midlayer3_minwidth=6 midlayer3_maxwidth=6 midlayer3_prefwidth=6 midlayer4_minwidth=6 midlayer4_maxwidth=6 midlayer4_prefwidth=6 bottomlayer_minwidth=6 bottomlayer_maxwidth=6 bottomlayer_prefwidth=6 maxuncoupledlength=500
DiffPairsRouting DiffPairsRouting_LVDS [InNetClass('LVDS')] p2: maxlimit=5 minlimit=5 mostfreqgap=5 toplayer_minwidth=4 toplayer_maxwidth=5.2 toplayer_prefwidth=5.2 midlayer1_minwidth=4 midlayer1_maxwidth=5.2 midlayer1_prefwidth=5.2 midlayer2_minwidth=4 midlayer2_maxwidth=5.2 midlayer2_prefwidth=5.2 midlayer3_minwidth=4 midlayer3_maxwidth=5.2 midlayer3_prefwidth=5.2 midlayer4_minwidth=4 midlayer4_maxwidth=5.2 midlayer4_prefwidth=5.2 bottomlayer_minwidth=4 bottomlayer_maxwidth=5.2 bottomlayer_prefwidth=5.2 maxuncoupledlength=500
HoleSize [All] p1: absolutevalues=TRUE maxlimit=200 minlimit=5.9 maxpercent=80.000 minpercent=20.000
MinimumAnnularRing [All] p1: minimumring=3
MinimumSolderMaskSliver [All] p1: minsoldermaskwidth=2
PlaneConnect [All] p1: planeconnectstyle=Direct reliefexpansion=20 reliefentries=4 reliefconductorwidth=10 reliefairgap=10
PolygonConnect [All] p1: connectstyle=Direct reliefconductorwidth=10 reliefentries=4 polygonreliefangle="90 Angle" airgapwidth=10
RoomDefinition "Copper to PMIC IC" [All] p1: confinementstyle=ConfineIn formatcopy=TRUE lockcomponents=FALSE outline 1421.5,1231.65 1686.44,1231.65 1686.44,914.22 1421.5,914.22
RoomDefinition DUT [InComponentClass('DUT')] p2: confinementstyle=ConfineIn formatcopy=TRUE lockcomponents=FALSE outline 3046.69,814.25 2272.5,814.25 2228.68,858.9 2228.68,1299.21 2052.17,1299.21 2052.17,1299.2 2052.17,1733.31 3043.03,1733.31
RoomDefinition COUPLE [WithinRoom('CO_PLANNER')] p3: confinementstyle=ConfineOut formatcopy=TRUE lockcomponents=FALSE outline 1578.38,2327.87 1578.38,2213.88 1578.37,2213.87 1968.78,2213.87 1968.78,2134.62 2365.38,2134.62 2365.38,2327.86 1578.37,2327.86
RoutingVias [All] p1: holewidth=28 width=50 viastyle="Through Hole" minholewidth=5 minwidth=15 maxholewidth=28 maxwidth=50
SilkToBoardRegionClearance [Not ((IsComment or IsDesignator) And (Hide <> 'False')) and not InRegion(1000,500,4000,800)] p1:
SilkToSilkClearance [All] p1: silktosilkclearance=3
SilkToSolderMaskClearance [IsPad] p1: minsilkscreentomaskgap=3 clearancetoexposedcopper=TRUE
SolderMaskExpansion [All] p1: expansion=0
Width [All] p1: maxlimit=100 minlimit=4 preferedwidth=10
22 further rules are at their usual default settings.

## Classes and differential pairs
net class USB: XDSET_1_D_N XDSET_1_D_P
net class Undefined: NetR128_2
net class SPI: AR_CS1 AR_HOSTINTR1 AR_MISO1 AR_MOSI1 AR_SPICLK1 CS1 D_LOGGER MISO1 MOSI1 NetJ1_7 NetJ1_9 NetJ1_10 NetJ1_11 NetJ1_12 NetJ5_13 NetJ6_12 NetJ6_14 NetJ6_16 SPICLK1
net class RF: RX1 RX2 RX3 RX4 TX1 TX2 TX3
net class QSPI: AR_QSPI_CS AR_QSPI_D0 AR_QSPI_D1 AR_QSPI_D2 AR_QSPI_D3 AR_QSPI_SCLK NetR39_2 NetR40_1 NetR42_2 NetR44_1 NetR45_1
net class PWR: 3V3_BRD 3V3_MON_XDS_1 5V_IN 5V_UNREG +3.3VD AR_1P3_RF1 AR_1P3_RF2 AR_1V2 AR_1V4_APLL AR_1V4_SYNTH AR_1V8 AR_VBGAP AR_VOUT_PA GND MCU_3V3 MCU_5V NetC1_2 NetC18_2 NetC26_1 NetC28_1 NetC46_1 NetC78_1 NetC79_2 NetF1_2 PGOOD PMIC_1V0 PMIC_1V2 PMIC_1V8 PMICOUT_3V3 PMICVIO_3V3 VDDC_1 XDSET_1_VBUS XDSET_VBAT XDSET_VREFA
net class LVDS: AR_LVDS_VALID_N AR_LVDS_VALID_P AR_LVDSCSI0_N AR_LVDSCSI0_P AR_LVDSCSI1_N AR_LVDSCSI1_P AR_LVDSCSI2_N AR_LVDSCSI2_P AR_LVDSCSI3_N AR_LVDSCSI3_P AR_LVDSCSI_CLK_N AR_LVDSCSI_CLK_P AR_LVDSCSI_FRCLK_N AR_LVDSCSI_FRCLK_P HD_LVDS_VALID_N HD_LVDS_VALID_P HD_LVDSCSI0_N HD_LVDSCSI0_P HD_LVDSCSI1_N HD_LVDSCSI1_P HD_LVDSCSI2_N HD_LVDSCSI2_P HD_LVDSCSI3_N HD_LVDSCSI3_P HD_LVDSCSI_CLK_N HD_LVDSCSI_CLK_P HD_LVDSCSI_FRCLK_N HD_LVDSCSI_FRCLK_P
net class JTAG: AR_TCK AR_TDI AR_TDO_SOP0 AR_TMS NetJ1_4 NetJ1_5 NetJ1_6 NetJ1_8 XDSET_TCK XDSET_TDI XDSET_TDO XDSET_TMS
net class GENERAL: AR_ANAMUX AR_ANATEST1 AR_ANATEST2 AR_ANATEST3 AR_ANATEST4 AR_BSS_LOGGER AR_GPIO_0 AR_GPIO_1 AR_GPIO_2 AR_MSS_LOGGER AR_NERR_OUT AR_NERRIN AR_NRST AR_RS232RX AR_RS232TX AR_SCL AR_SDA AR_SYNC_IN AR_SYNC_OUT_SOP1 AR_VSENSE AR_WARMRST LDO_01_EN LDO_02_EN MCU_SOP0 MCU_SOP1 MCU_SOP2 NetC22_1 NetC71_2 NetC86_2 NetC87_2 NetC88_2 NetC89_2 NetD2_1 NetDS1_1 NetDS2_1 NetDS3_1 NetDS3_2 NetDS4_1 NetDS4_2 NetDS5_1 NetJ1_13 NetJ1_14 NetJ1_16 NetJ5_6 NetJ5_8 NetJ5_9 NetJ5_10 NetJ5_12 NetJ5_14 NetJ5_15 NetJ5_16 NetJ5_18 NetJ5_19 NetJ6_1 NetJ6_3 NetJ6_8 NetJ6_9 NetJ6_10 NetJ6_11 NetJ6_13 NetJ6_15 NetJ6_17 NetJ6_18 NetJ6_19 NetQ1_1 NetQ2_1 NetR68_1 NetR72_1 NetR79_2 NetR86_1 NetR88_2 NetR95_1 NetR98_2 NetR123_1 NetR124_1 NetR126_1 NetR127_1 NetR129_2 NetR143_1 NetR144_2 NetR146_1 NetR147_1 NetR152_1 NetR194_2 NetR197_2 NetR198_2 PGOOD PMIC_EN1 PMIC_EN2 PMIC_EN3 PMIC_NRST SS_CTRL SW0 SW1 SW2 SW3 VBUS_1_DETECT XDSET_1_ID XDSET_LOGGER XDSET_NRST
net class CLK: AR_MCUCLKOUT AR_OSC_CLKOUT AR_PMIC_CLKOUT_SOP2 AR_XTALM AR_XTALP NetJ2_1 NetJ5_20 NetJ6_5 PMIC_CLK XDSET_OSC0 XDSET_OSC1
net class CAN: CAN_RX CAN_TX NetC24_2 NetJ3_1 NetJ3_3 NetR11_2 NetR12_2
component class "PROC010B_XDS110 Interface_1B": C49 C63 C66 C67 C70 C71 R123 R124 R126 R127 R128 R129 R134 R135 R136 R140 R152 R154 R155 R194 U6 U7 Y2
component class "PROC010B_XDS110 Interface_1A": C41 C42 C43 C50 C61 C62 C64 C69 C74 C75 C76 C77 C78 C79 C80 J8 R151 R153 R156 R157 R158 R159 R161 R174 R175 R176 U9 U10
component class PROC010B_Tempsensor: C84 C85 R179 R180 R181 R182 R183 R184 R185 R186 R187 R188 U11 U12
component class PROC010B_Decoupling_Caps_Reference: C3 C4 C5 C6 C7 C10 C12 C13 C14 C17 C39 C45 C47 C48 C51 C52 C53 C56 C57 C58 C65 C83
component class PROC010B_QSPI_Flash_Reference: C1 C2 R37 R38 R39 R40 R41 R42 R43 R44 R45 U1
component class PROC010B_Pwr_RST_LEDs: C11 C26 C27 D2 D3 DS1 DS2 DS3 DS4 DS5 F1 FB1 FB2 P5 P6 Q1 Q2 R68 R72 R73 R74 R77 R79 R80 R90 R100 R103 R110 R116 R117 R118 R130 R133 R160 R189 SW1 SW2
component class PROC010B_PMIC_Reference: C54 C55 C59 C60 C68 C72 C73 C81 C82 C86 C87 C88 C89 L1 L2 L3 L4 R138 R139 R141 R142 R143 R144 R145 R146 R147 R148 R149 R150 R190 R191 R192 R193 U8
component class "PROC010B_LP Connector": J4 J5 J6 J7 P1 R1 R2 R3 R4 R5 R6 R8 R9 R10 R18 R19 R24 R25 R26 R31 R32 R35 R36 R76 R94 R102 R104 R105 R106 R107 R108 R109 R115 R162 R163 R164 R165 R166 R167 R168 R169 R172 R173
component class PROC010B_LDO: C18 C21 C22 C23 C25 C28 C29 C30 C31 C32 C35 C37 C40 C44 C46 R46 R47 R81 R82 R83 R84 R119 R120 R121 R122 R131 R132 U4 U5
component class "PROC010B_HD Connector": J1 J2 R7 R17 R20 R21 R22 R23 R27 R28 R29 R30 R33 R34 R48 R49 R50 R51 R52 R53 R54 R55 R56 R57 R58 R59 R60 R61 R62 R63 R64 R65 R66 R67 R69 R70 R71 R75 R111
component class PROC010B_SOP_Headers_Reference: P2 P3 P4 R88 R89 R92 R93 R95 R96 R97 R98 R99 R101 R112 R113 R114
component class "PROC010B_CAN Interface": C16 C20 C24 C90 J3 R11 R12 R78 R85 R86 R87 R125 R177 R178 R195 S1 U3 U13
component class Header: P1 P2 P3 P4 P5
component class Label: LBL1
component class AssemblyNote: ZZ1 ZZ2 ZZ3 ZZ4 ZZ5
component class FiducialMark: FID1 FID2 FID3 FID4 FID5 FID6 FID7
component class PROC010B_Hardware: "CAUTION HOT SURFACE1" "ESD Susceptible1" FID1 FID2 FID3 FID4 FID5 FID6 FID7 LBL1 Logo1 Logo2 Logo3 LOGO4 ZZ1 ZZ2 ZZ3 ZZ4 ZZ5
component class Logo: Logo1
polygon class ANTP: TOP-RX1 TOP-RX2 TOP-RX3 TOP-RX4 TOP-TX1 TOP-TX2 TOP-TX3
component class PROC010B_DUT_Reference: C8 C9 C15 R13 R14 R15 R16 R91 R170 R171 R196 R197 R198 TP1 TP2 U2 Y1
component class PROC010B_LC_Filtering_Reference: C19 C33 C34 C36 C38 C91 L5 L7 L8 L9 R137
differential pair XDSET_1_D: +XDSET_1_D_P -XDSET_1_D_N
differential pair HD_LVDSCSI_FRCLK: +HD_LVDSCSI_FRCLK_P -HD_LVDSCSI_FRCLK_N
differential pair HD_LVDSCSI_CLK: +HD_LVDSCSI_CLK_P -HD_LVDSCSI_CLK_N
differential pair HD_LVDSCSI3: +HD_LVDSCSI3_P -HD_LVDSCSI3_N
differential pair HD_LVDSCSI2: +HD_LVDSCSI2_P -HD_LVDSCSI2_N
differential pair HD_LVDSCSI1: +HD_LVDSCSI1_P -HD_LVDSCSI1_N
differential pair HD_LVDSCSI0: +HD_LVDSCSI0_P -HD_LVDSCSI0_N
differential pair HD_LVDS_VALID: +HD_LVDS_VALID_P -HD_LVDS_VALID_N
differential pair AR_LVDSCSI_FRCLK: +AR_LVDSCSI_FRCLK_P -AR_LVDSCSI_FRCLK_N
differential pair AR_LVDSCSI_CLK: +AR_LVDSCSI_CLK_P -AR_LVDSCSI_CLK_N
differential pair AR_LVDSCSI3: +AR_LVDSCSI3_P -AR_LVDSCSI3_N
differential pair AR_LVDSCSI2: +AR_LVDSCSI2_P -AR_LVDSCSI2_N
differential pair AR_LVDSCSI1: +AR_LVDSCSI1_P -AR_LVDSCSI1_N
differential pair AR_LVDSCSI0: +AR_LVDSCSI0_P -AR_LVDSCSI0_N
differential pair AR_LVDS_VALID: +AR_LVDS_VALID_P -AR_LVDS_VALID_N

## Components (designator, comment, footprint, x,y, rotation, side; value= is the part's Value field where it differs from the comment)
C1 "GCM188R71C105KA64D" 0603 2055.47,2088.99 r180 top value=1uF
C2 "CGA2B3X7R1H104K050BB" 0402L 2030.78,1995.26 r180 top value=0.1uF
C3 "GCM155R71C224KE02D" 0402L 2381.16,1770.8 r0 top value=0.22uF
C4 "GCM155R71C104KA55D" 0402L 2108,1747.43 r90 top value=0.1uF
C5 "GCM155R71C224KE02D" 0402L 2166.55,1745.78 r90 top value=0.22uF
C6 "GCM155R71C104KA55D" 0402 2042.55,1737.8 r90 top value=0.1uF
C7 "GCM155R71C224KE02D" 0402L 1978.55,1732.41 r90 top value=0.22uF
C8 "C0603X7S1A104K030BC" 0201_033 184.69,1666.75 r180 top value=0.1uF
C9 "GJM1555C1H4R7BB01D" 0402 1893.4,1321.21 r270 top value=4.7pF
C10 "GCM155R71C224KE02D" 0402 2473,1240 r0 top value=0.22uF
C11 "GCM155R71C104KA55D" 0402L 195.7,1211.25 r90 top value=0.1uF
C12 "GCM155R71C224KE02D" 0402 2182.55,1205.8 r270 top value=0.22uF
C13 "GCM188R71C105KA64D" 0603 2234.45,1191.9 r270 top value=1uF
C14 "GCM188R71C105KA64D" 0603 2115.45,1189.8 r270 top value=1uF
C15 "GJM1555C1H4R7BB01D" 0402 2003.47,1178.2 r0 top value=4.7pF
C16 "C0402C104K8RACTU" 0402L 1111.7,1119.67 r180 top value=0.1uF
C17 "GCM21BR71A106KE22L" 0805_HV 2196.81,1077.38 r0 top value=10uF
C18 "GCM188R71C474KA55D" 0603 2059.87,1034.87 r180 top value=0.47uF
C19 "GCM21BR71A106KE22L" 0805_HV 2196.23,984.99 r0 top value=10uF
C20 "C0402C104K8RACTU" 0402L 968.28,835.45 r0 top value=0.1uF
C21 "CGA2B3X7R1H104K050BB" 0402 2117.99,720.01 r0 top value=0.1uF
C22 "GCM188R71C474KA55D" 0603 1958.47,790.27 r180 top value=0.47uF
C23 "GCM21BR71A106KE22L" 0805_HV 2114.63,650.9 r0 top value=10uF
C24 "C1005X7R1H472K050BA" 0402L 1112.06,711.14 r180 top value=4700pF
C25 "CGA5L1X7R0J226M160AC" 1206_180 2111.8,563.22 r0 top value=22uF
C26 "T491B476K010AT" 3528-21 1677.7,-0.35 r270 top value=47uF
C27 "T491B476K010AT" 3528-21 1534.3,-1.55 r270 top value=47uF
C28 "CGA2B3X8R1H103K050BB" 0402L 1732.83,1927.64 r0 bottom value=0.01uF
C29 "CGA2B3X8R1H103K050BB" 0402L 1511.34,1620.25 r0 top value=0.01uF
C30 "CGA5L1X7R0J226M160AC" 1206_180 1402,1796.5 r270 bottom value=22uF
C31 "CGA5L1X7R0J226M160AC" 1206_180 1310.2,1796.25 r270 bottom value=22uF
C32 "GCM21BR71A106KE22L" 0805 1487.95,1795 r270 bottom value=10uF
C33 "GCM188R71C105KA64D" 0603 1802.6,1785.62 r270 bottom value=1uF
C34 "GCM21BR71A106KE22L" 0805_HV 1875,1790 r270 bottom value=10uF
C35 "GCM21BR71A106KE22L" 0805_HV 1955,1790 r270 bottom value=10uF
C36 "GCM188R71C105KA64D" 0603 1802.53,1642.85 r90 bottom value=1uF
C37 "GCM21BR71A106KE22L" 0805_HV 1955,1640.8 r90 bottom value=10uF
C38 "GCM21BR71A106KE22L" 0805_HV 1875,1640.8 r90 bottom value=10uF
C39 "GCM155R71C224KE02D" 0402L 2465,1595 r0 bottom value=0.22uF
C40 "GCM21BR71A106KE22L" 0805_HV1 1489.95,1632.3 r90 bottom value=10uF
C41 "C1005X7S0J105M050BC" 0402L 558.3,1631.85 r270 bottom value=1uF
C42 "C0402C104K8RACTU" 0402L 518.22,1631.85 r270 bottom value=0.1uF
C43 "C0402C104K8RACTU" 0402L 362.52,1629.85 r270 bottom value=0.1uF
C44 "CGA2B3X8R1H103K050BB" 0402L 1559.98,1834.93 r0 top value=0.01uF
C45 "GCM21BR71A106KE22L" 0805_HV1 2575,1570 r180 bottom value=10uF
C46 "CGA2B3X8R1H103K050BB" 0402L 1728.5,1566.52 r0 bottom value=0.01uF
C47 "GCM155R71C224KE02D" 0402L 2465,1555 r0 bottom value=0.22uF
C48 "GCM155R71C224KE02D" 0402 2077.55,1552.7 r90 bottom value=0.22uF
C49 "C0402C104K8RACTU" 0402L 894.35,1481.9 r180 bottom value=0.1uF
C50 "C1005X7R1E103K050BB" 0402L 126.65,1429.4 r0 bottom value=0.01uF
C51 "GCM155R71C224KE02D" 0402 2435.27,1426.58 r270 bottom value=0.22uF
C52 "GCM21BR71A106KE22L" 0805_HV 2498.15,1421.4 r270 bottom value=10uF
C53 "GCM155R71C224KE02D" 0402 2093.35,1414 r180 bottom value=0.22uF
C54 "GCM31CR71A226KE02" 1206_180 1592.83,1428.59 r90 bottom value=22uF
C55 "GCM31CR71A226KE02" 1206_180 1506.18,1429.62 r90 bottom value=22uF
C56 "GCM155R71C224KE02D" 0402 2153.83,1313.3 r180 bottom value=0.22uF
C57 "GCM155R71C224KE02D" 0402 2458.2,1287.95 r270 bottom value=0.22uF
C58 "GCM21BR71A106KE22L" 0805 2541.18,1281.31 r270 bottom value=10uF
C59 "GCM21BR71A106KE22L" 0805_HV1 1480.85,1272.15 r180 bottom value=10uF
C60 "GCM21BR71A106KE22L" 0805_HV1 1621.95,1271.3 r0 bottom value=10uF
C61 "C1005X7S0J105M050BC" 0402L 127.65,1240.06 r0 bottom value=1uF
C62 "C1005X7S0J105M050BC" 0402L 894.65,1201.5 r180 bottom value=1uF
C63 "GRM1555C1H8R0DA01D" 0402L 1041.3,994.36 r180 bottom value=8pF
C64 "C0402C104K8RACTU" 0402L 894.65,1158.3 r180 bottom value=0.1uF
C65 "GCM21BR71A106KE22L" 0805_HV 2476.6,1139.95 r270 bottom value=10uF
C66 "C0402C103K4RACTU" 0402L 127.19,1130.1 r0 bottom value=0.01uF
C67 "C0402C104K8RACTU" 0402L 127.25,1088.8 r0 bottom value=0.1uF
C68 "GCM155R71C224KE02D" 0402L 1739.45,1067 r180 bottom value=0.22uF
C69 "C0402C103K4RACTU" 0402L 127.65,1003.56 r0 bottom value=0.01uF
C70 "GRM1555C1H8R0DA01D" 0402L 975,1179.85 r270 bottom value=8pF
C71 "C0402C104K8RACTU" 0402L 814,1010.5 r180 top value=0.1uF
C72 "GCM21BR71A106KE22L" 0805_HV1 1618.65,868.7 r0 bottom value=10uF
C73 "GCM21BR71A106KE22L" 0805_HV1 1479.85,868.7 r180 bottom value=10uF
C74 "C1005X7S1A225K050BC" 0402_065L 515.6,862.15 r90 bottom value=2.2uF
C75 "C0402C104K8RACTU" 0402L 472.68,862.15 r90 bottom value=0.1uF
C76 "C0402C104K8RACTU" 0402L 361.92,861.85 r90 bottom value=0.1uF
C77 "C1005X7S1A225K050BC" 0402_065L 107.82,859.15 r270 bottom value=2.2uF
C78 "04025A150FAT2A" 0402L 67.1,859.15 r270 bottom value=15pF
C79 "C0402C104K8RACTU" 0402L 25.62,858.85 r270 bottom value=0.1uF
C80 "C1005X7S1A225K050BC" 0402_065L -15.4,858.5 r270 bottom value=2.2uF
C81 "GCM31CR71A226KE02" 1206_180 1499.96,711.43 r270 bottom value=22uF
C82 "GCM31CR71A226KE02" 1206_180 1597.69,711.75 r270 bottom value=22uF
C83 "GCM21BR71A106KE22L" 0805_HV 2470.42,1141.98 r270 top value=10uF
C84 "C0402C104K8RACTU" 0402L 1739.35,1066.5 r180 top value=0.1uF
C85 "C0402C104K8RACTU" 0402L 241.11,913.35 r270 top value=0.1uF
C86 "CGA2B2NP01H391J050BA" 0402L 1421.7,1265.35 r180 top value=390pF
C87 "CGA2B2NP01H391J050BA" 0402L 1735,1269.65 r270 top value=390pF
C88 "CGA2B2NP01H391J050BA" 0402L 1364.7,867.65 r90 top value=390pF
C89 "CGA2B2NP01H391J050BA" 0402L 1735.6,865.35 r90 top value=390pF
C90 "C0402C104K8RACTU" 0402L 1216.27,1201.97 r180 top value=0.1uF
C91 "GCM188R71C105KA64D" 0603 1933.5,1034.87 r0 top value=1uF
"CAUTION HOT SURFACE1" "CAUTION HOT SURFACE" IEC_HotSurface_Small 2223.32,2025.12 r0 top
D2 "SMS3923-040LF" SOD-882 45.81,1106.06 r0 top locked value=V
D3 "SZP6SMB6.8AT3G" SMB 1524.64,696.5 r0 top value=5.8V
DS1 "SML-LX0603SRW-TR" SML-LX0603SRW_SuperRed 119.71,609.17 r90 top value="Super Red"
DS2 "SML-LX0603SRW-TR" SML-LX0603SRW_SuperRed 234.35,614.83 r90 top value="Super Red"
DS3 "SML-E12Y8WT86" SML-E1_Yellow 15.8,607.06 r270 top value=Yellow
DS4 "SML-E12Y8WT86" SML-E1_Yellow 255.01,402.19 r270 top value=Yellow
DS5 "SML-LX0603SRW-TR" SML-LX0603SRW_SuperRed 33.45,275.58 r90 top value="Super Red"
"ESD Susceptible1" "ESD Susceptible" ESD_Overlay_Small 806.3,333.85 r0 top
F1 "0440005.WR" 1206 1360,300 r180 top
FB1 "BLM21PG300SH1D" 0805_HV 1455.18,483.01 r0 top value="30 ohm"
FB2 "BLM21PG300SH1D" 0805_HV 1455.18,565.13 r0 top value="30 ohm"
FID1 "Fiducial" Fiducial10-20 225,2200 r90 bottom
FID2 "Fiducial" Fiducial10-20 200,70 r90 bottom
FID3 "Fiducial" Fiducial10-20 2925,2008 r90 bottom
FID4 "Fiducial" Fiducial10-20 2140,80 r90 top
FID5 "Fiducial" Fiducial10-20 2140,80 r90 bottom
FID6 "Fiducial" Fiducial10-20 225.13,2099.98 r90 top
FID7 "Fiducial" Fiducial10-20 200,175 r90 top
J1 "QSH-030-01-L-D-A" Samtec_QSH-030-01-X-D-A 814.05,1886.26 r270 top locked
J2 "128-0711-201" Johnson_128-0711-201 2158.71,293.72 r0 top
J3 "OSTTE030161" On-Shore_OSTTE030161 670.6,-21.34 r0 top
J4 "SSM-103-S-SV" Samtec_SSM-103-x-SV 1727.5,2159.5 r0 bottom
J5 "SSM-110-S-DV" Samtec_SSM-110-x-DV 977.5,409.5 r0 bottom locked
J6 "SSM-110-S-DV" Samtec_SSM-110-x-DV 977.5,2109.5 r0 bottom locked
J7 "SSM-103-S-SV" Samtec_SSM-103-x-SV 1727.5,359.5 r0 bottom
J8 "105017-0001" CONN_105017-0001 1945,-52.27 r180 bottom locked
L1 "DFE252012P-R47M=P2" DFE252012P 1694.05,1366.3 r90 bottom value=470nH
L2 "DFE252012P-R47M=P2" DFE252012P 1407.85,1376.9 r90 bottom value=470nH
L3 "DFE252012P-R47M=P2" DFE252012P 1693.55,761.8 r270 bottom value=470nH
L4 "DFE252012P-R47M=P2" DFE252012P 1401.55,761.8 r270 bottom value=470nH
L5 "NLCV32T-R10M-EFRD" NLCV32 1677.4,1699.74 r0 bottom value=100nH
L7 "NLCV32T-R10M-EFRD" NLCV32 2185,845 r90 top value=100nH
L8 "NLCV32T-R10M-EFRD" NLCV32 1677.4,1817.43 r0 bottom value=100nH
L9 "NLCV32T-R10M-EFRD" NLCV32 1740.13,1487.07 r0 bottom value=100nH
LBL1 "Label" Label_650x200 2713.27,681.66 r0 top locked
Logo1 "Texas Instruments" TI_Stacked_Overlay_Small 2640.11,492.24 r0 top
Logo2 "FCC disclaimer" FCC_disclaimer 2273.36,2458.06 r0 top
Logo3 "WEEE logo" WEEE_Minimum 2864.39,277.26 r0 top
LOGO4 "CE Mark" CE_Mark_5mm 2502.7,-21.5 r0 top
P1 "TSW-103-07-T-S" Samtec_TSW-103-07-T-S 31.94,1674.53 r270 top
P2 "TSW-102-07-G-S" TSW-102-07-G-S 612.44,719.75 r90 top
P3 "TSW-102-07-G-S" TSW-102-07-G-S 409,719.42 r90 top
P4 "TSW-102-07-G-S" TSW-102-07-G-S 818.44,718.75 r90 top
P5 "TSW-102-07-G-S" TSW-102-07-G-S 1610,215 r0 top
P6 "PJ-002AH" CUI_PJ-002AH 1180,16.89 r270 top
Q1 "BSS123" SOT-23 120.58,472.75 r90 top value=100V
Q2 "BSS123" SOT-23 120.62,472.17 r90 bottom value=100V
R1 "CRCW02010000Z0ED" 0201_Silk 730.05,2242.72 r270 top value=0
R2 "CRCW02010000Z0ED" 0201_Silk 930.05,2242.72 r270 top value=0
R3 "CRCW02010000Z0ED" 0201_Silk 1092.38,2242.72 r270 top value=0
R4 "CRCW02010000Z0ED" 0201_Silk 1022.55,2242.72 r270 top value=0
R5 "CRCW02010000Z0ED" 0201_Silk 1054.91,2242.72 r270 top value=0
R6 "CRCW02010000Z0ED" 0201_Silk 1129,2242.72 r270 top value=0
R7 "CRCW02010000Z0ED" 0201_Silk 962.11,1611.72 r270 top value=0
R8 "CRCW02010000Z0ED" 0201_Silk 1329.55,2242.72 r270 top value=0
R9 "CRCW02010000Z0ED" 0201_Silk 829.75,2241.72 r270 top value=0
R10 "CRCW02010000Z0ED" 0201_Silk 1239.25,2241.72 r270 top value=0
R11 "ERJ-2GE0R00X" 0402L 1196.59,1264.15 r0 top value=0
R12 "ERJ-2GE0R00X" 0402L 1015.51,1118 r270 top value=0
R13 "CRCW040210K0FKED" 0402L 1198.4,2234.05 r270 top value=10.0k
R14 "CRCW040210K0FKED" 0402L 638.26,2215.06 r270 top value=10.0k
R15 "CRCW040210K0FKED" 0402L 1042.8,2179.56 r0 top value=10.0k
R16 "CRCW040210K0FKED" 0402L 638.2,2137.15 r90 top value=10.0k
R17 "CRCW02010000Z0ED" 0201_Silk 1060.25,2130.72 r270 top value=0
R18 "CRCW02010000Z0ED" 0201_Silk 1028.21,2130.07 r270 top value=0
R19 "CRCW02010000Z0ED" 0201_Silk 419.25,2129.72 r270 top value=0
R20 "CRCW02010000Z0ED" 0201_Silk 452.11,2129.72 r270 top value=0
R21 "CRCW02010000Z0ED" 0201_Silk 484.35,2129.72 r270 top value=0
R22 "CRCW02010000Z0ED" 0201_Silk 550.11,2129.72 r270 top value=0
R23 "CRCW02010000Z0ED" 0201_Silk 585.61,2129.72 r270 top value=0
R24 "CRCW02010000Z0ED" 0201_Silk 679.75,2129.72 r270 top value=0
R25 "CRCW02010000Z0ED" 0201_Silk 726.25,2129.72 r270 top value=0
R26 "CRCW02010000Z0ED" 0201_Silk 834.11,2129.72 r270 top value=0
R27 "CRCW02010000Z0ED" 0201_Silk 866.61,2129.72 r270 top value=0
R28 "CRCW02010000Z0ED" 0201_Silk 899.11,2129.72 r270 top value=0
R29 "CRCW02010000Z0ED" 0201_Silk 963.83,2129.72 r270 top value=0
R30 "CRCW02010000Z0ED" 0201_Silk 995.75,2129.72 r270 top value=0
R31 "CRCW02010000Z0ED" 0201_Silk 1184,2129.68 r270 top value=0
R32 "CRCW02010000Z0ED" 0201_Silk 1277.55,2129.72 r270 top value=0
R33 "CRCW02010000Z0ED" 0201_Silk 517.39,2129.28 r270 top value=0
R34 "CRCW20100000Z0EF" 2010L 1415.06,2071.26 r0 top value=0
R35 "CRCW02010000Z0ED" 0201_Silk 1326.75,1976.72 r90 top value=0
R36 "CRCW02010000Z0ED" 0201_Silk 1427.25,1976.72 r90 top value=0
R37 "ERJ-2GE0R00X" 0402L 2030.93,2037.7 r180 top value=0
R38 "CRCW040247K5FKED" 0402L 1657.69,2052.34 r180 top value=47.5k
R39 "CRCW020133R2FNED" 0201_Silk 1664.78,1992.45 r0 top value=33.2
R40 "CRCW020133R2FNED" 0201_Silk 2022.78,1888.35 r0 top value=33.2
R41 "CRCW040210K0FKED" 0402L 2091.65,1884.48 r0 top value=10.0k
R42 "CRCW020133R2FNED" 0201_Silk 1664.78,1956.85 r0 top value=33.2
R43 "CRCW040210K0FKED" 0402L 1596.29,1950.4 r180 top value=10.0k
R44 "CRCW020133R2FNED" 0201_Silk 2022.78,1853.85 r0 top value=33.2
R45 "CRCW020133R2FNED" 0201_Silk 2023.78,1807.35 r0 top value=33.2
R46 "CRCW040210K0FKED" 0402L 1468.54,1756.11 r180 top value=10.0k
R47 "CRCW040210K0FKED" 0402L 1468.54,1788.74 r0 top value=10.0k
R48 "CRCW02010000Z0ED" 0201_Silk 475.61,1611.72 r270 top value=0
R49 "CRCW02010000Z0ED" 0201_Silk 508.25,1611.72 r270 top value=0
R50 "CRCW02010000Z0ED" 0201_Silk 540.75,1611.72 r270 top value=0
R51 "CRCW02010000Z0ED" 0201_Silk 573.25,1611.72 r270 top value=0
R52 "CRCW02010000Z0ED" 0201_Silk 605.75,1611.72 r270 top value=0
R53 "CRCW02010000Z0ED" 0201_Silk 638.25,1611.72 r270 top value=0
R54 "CRCW02010000Z0ED" 0201_Silk 671.35,1611.72 r270 top value=0
R55 "CRCW02010000Z0ED" 0201_Silk 703.85,1611.72 r270 top value=0
R56 "CRCW02010000Z0ED" 0201_Silk 735.75,1611.72 r270 top value=0
R57 "CRCW02010000Z0ED" 0201_Silk 768.05,1611.72 r270 top value=0
R58 "CRCW02010000Z0ED" 0201_Silk 800.55,1611.72 r270 top value=0
R59 "CRCW02010000Z0ED" 0201_Silk 833.05,1611.72 r270 top value=0
R60 "CRCW02010000Z0ED" 0201_Silk 865.55,1611.72 r270 top value=0
R61 "CRCW02010000Z0ED" 0201_Silk 897.75,1611.72 r270 top value=0
R62 "CRCW02010000Z0ED" 0201_Silk 929.85,1611.72 r270 top value=0
R63 "CRCW02010000Z0ED" 0201_Silk 1161.25,2242.72 r270 top value=0
R64 "CRCW02010000Z0ED" 0201_Silk 1026.61,1611.72 r270 top value=0
R65 "CRCW02010000Z0ED" 0201_Silk 1059.25,1611.72 r270 top value=0
R66 "CRCW02010000Z0ED" 0201_Silk 1091.75,1611.72 r270 top value=0
R67 "CRCW02010000Z0ED" 0201_Silk 1124.25,1611.72 r270 top value=0
R68 "ERJ-2GEJ101X" 0402L 246.04,1553.15 r90 top value=100
R69 "CRCW02010000Z0ED" 0201_Silk 1044.1,1563.62 r180 top value=0
R70 "CRCW02010000Z0ED" 0201_Silk 1091.33,1551.72 r270 top value=0
R71 "CRCW02010000Z0ED" 0201_Silk 1124.33,1551.72 r270 top value=0
R72 "CRCW02010000Z0ED" 0201_Silk 192.5,1461.25 r90 top value=0
R73 "CRCW040210K0FKED" 0402L 192.05,1390.92 r90 top value=10.0k
R74 "CRCW040210K0FKED" 0402L 51.65,1221.14 r180 top value=10.0k
R75 "CRCW02010000Z0ED" 0201_Silk 904.07,1260.47 r90 bottom value=0
R76 "CRCW02010000Z0ED" 0201_Silk 941.93,1260.47 r90 bottom value=0
R77 "ERJ-2GEJ101X" 0402L -27.74,1188.85 r270 top value=100
R78 "ERJ-2GE0R00X" 0402L 1111.7,1088.29 r0 top value=0
R79 "ERJ-2GEJ101X" 0402L 285.35,1098.84 r180 top value=100
R80 "ERJ-2GEJ101X" 0402L -27.26,1087.15 r90 top value=100
R81 "CRCW040210K0FKED" 0402L 1989.89,1085.17 r0 top value=10.0k
R82 "CRCW040212K7FKED" 0402L 2065.31,1085.13 r0 top value=12.7k
R83 "CRCW040210K0FKED" 0402 1927.35,892.02 r0 top value=10.0k
R84 "CRCW040210K0FKED" 0402 1927.35,851.22 r180 top value=10.0k
R85 "CRCW040261R9FKED" 0402L 1142.37,766.8 r90 top value=61.9
R86 "CRCW040210K0FKED" 0402L 1192.37,766.8 r270 top value=10.0k
R87 "CRCW040261R9FKED" 0402L 1092.37,766.8 r270 top value=61.9
R88 "CRCW040282K5FKED" 0402L 941.42,759.15 r270 top value=82.5k
R89 "CRCW040210K0FKED" 0402L 981.88,758.85 r270 top value=10.0k
R90 "ERJ-2GEJ361X" 0402L 200.46,737.79 r90 top value=360
R91 "CRCW040210K0FKED" 0402L 149,737.88 r90 top value=10.0k
R92 "CRCW04027K87FKED" 0402L 940.92,681.15 r270 top value=7.87k
R93 "CRCW0402750RFKED" 0402L 981.12,680.36 r270 top value=750
R94 "CRCW02010000Z0ED" 0201_Silk 828.25,532.28 r90 top value=0
R95 "CRCW04027K87FKED" 0402L 648.82,524.55 r90 top value=7.87k
R96 "CRCW040282K5FKED" 0402L 608.78,524.25 r270 top value=82.5k
R97 "ERJ-2GE0R00X" 0402L 285,509.15 r90 top value=0
R98 "CRCW040210K0FKED" 0402L 325.82,508.36 r90 top value=10.0k
R99 "CRCW04027K87FKED" 0402L 409.62,509.15 r90 top value=7.87k
R100 "ERJ-2GEJ511X" 0402L 242.91,509.06 r270 top value=510
R101 "CRCW0402750RFKED" 0402L 366.98,508.85 r90 top value=750
R102 "CRCW02010000Z0ED" 0201_Silk 1230.25,500.28 r90 top value=0
R103 "ERJ-2GEJ511X" 0402L 7.57,500.07 r180 top value=510
R104 "CRCW02010000Z0ED" 0201_Silk 727.75,499.28 r90 top value=0
R105 "CRCW02010000Z0ED" 0201_Silk 929.75,499.28 r90 top value=0
R106 "CRCW02010000Z0ED" 0201_Silk 1030.25,499.28 r90 top value=0
R107 "ERJ-2GE0R00X" 0402L 1129.75,499.28 r90 top value=0
R108 "CRCW02010000Z0ED" 0201_Silk 1330.35,499.08 r90 top value=0
R109 "CRCW02010000Z0ED" 0201_Silk 1362.85,499.08 r90 top value=0
R110 "CRCW0402100KFKED" 0402L 7.72,459.77 r180 top value=100k
R111 "CRCW02010000Z0ED" 0201_Silk 2158.86,456.17 r270 top value=0
R112 "CRCW0402750RFKED" 0402L 649.32,447.55 r270 top value=750
R113 "CRCW040210K0FKED" 0402L 608.92,447.55 r90 top value=10.0k
R114 "CRCW040282K5FKED" 0402L 409.52,433.15 r90 top value=82.5k
R115 "CRCW20100000Z0EF" 2010 498.73,431.05 r270 top value=0
R116 "ERJ-2GEJ511X" 0402L 7.78,416.33 r0 top value=510
R117 "ERJ-2GEJ511X" 0402L 308.61,392.15 r90 top value=510
R118 "CRCW20100000Z0EF" 2010 1589.87,377.74 r0 top value=0
R119 "ERJ-2GE0R00X" 0402L 1577.96,1916.14 r270 bottom value=0
R120 "ERJ-2GE0R00X" 0402L 1546.63,1841.79 r270 bottom value=0
R121 "CRCW04023K00FKED" 0402L 1652.02,1893.62 r0 bottom value=3.00k
R122 "CRCW04021K96FKED" 0402L 1732.83,1893.62 r0 bottom value=1.96k
R123 "CRCW04021K00FKED" 0402L 757.28,1632.15 r90 bottom value=1.00k
R124 "CRCW04021K00FKED" 0402L 637.72,1631.85 r270 bottom value=1.00k
R125 "CRCW040210K0FKED" 0402L 1229.27,1234.12 r0 top value=10.0k
R126 "CRCW04021K00FKED" 0402L 717.68,1632.15 r90 bottom value=1.00k
R127 "CRCW04021K00FKED" 0402L 598.12,1631.85 r270 bottom value=1.00k
R128 "ERJ-2GE0R00X" 0402L 246.5,1628.85 r270 bottom value=0
R129 "ERJ-2GE0R00X" 0402L 287,1628.5 r270 bottom value=0
R130 "MCT06030Z0000ZP500" 0603 1390.31,1598.71 r180 bottom value=0
R131 "CRCW04021K96FKED" 0402L 1728.74,1601.78 r0 bottom value=1.96k
R132 "CRCW04023K00FKED" 0402L 1650.78,1566.52 r0 bottom value=3.00k
R133 "MCT06030Z0000ZP500" 0603 1388.69,1529.05 r180 bottom value=0
R134 "CRCW040249R9FKED" 0402L 894.65,1440.6 r0 bottom value=49.9
R135 "CRCW02010000Z0ED" 0201_Silk 134.78,1366.19 r0 bottom value=0
R136 "CRCW02010000Z0ED" 0201_Silk 134.78,1334.29 r0 bottom value=0
R137 "MCT06030Z0000ZP500" 0603 2628.57,1278.19 r270 bottom value=0
R138 "CRCW0402100KFKED" 0402L 1357.78,1221.96 r270 bottom value=100k
R139 "CRCW04021K96FKED" 0402L 1863.35,1207.54 r180 bottom value=1.96k
R140 "CRCW04021K00FKED" 0402L 127.65,1199.52 r0 bottom value=1.00k
R141 "ERJ-2GE0R00X" 0402L 1413.4,1154.01 r180 bottom value=0
R142 "ERJ-2RKF4991X" 0402L 1863.35,1167.04 r180 bottom value=4.99k
R143 "CRCW04024K99FKED" 0402L 1786.35,1166.5 r0 bottom value=4.99k
R144 "CRCW02010000Z0ED" 0201_Silk 1368.78,1066.69 r0 bottom value=0
R145 "CRCW040210K0FKED" 0402L 1833.44,1080.15 r270 bottom value=10.0k
R146 "CRCW02010000Z0ED" 0201_Silk 1368.78,1099.19 r180 bottom value=0
R147 "CRCW04024K99FKED" 0402L 1774,1027.5 r0 bottom value=4.99k
R148 "CRCW040210K0FKED" 0402L 1875,1002.5 r90 bottom value=10.0k
R149 "ERJ-2GEJ102X" 0402L 1916.14,1002.15 r270 bottom value=1.0k
R150 "ERJ-2RKF4991X" 0402L 1833.74,1002.15 r270 bottom value=4.99k
R151 "CRCW0402330KFKED" 0402L 127.65,961.04 r180 bottom value=330k
R152 "ERJ-2GE0R00X" 0402L 814,1071.5 r0 top value=0
R153 "CRCW0402330KFKED" 0402L 127.65,917.74 r0 bottom value=330k
R154 "ERJ-2GEJ101X" 0402L 736,927.5 r270 top value=100
R155 "CRCW040210K0FKED" 0402L 692.78,861.15 r90 bottom value=10.0k
R156 "CRCW040249K9FKED" 0402L 158.03,739.19 r90 bottom value=49.9k
R157 "CRCW040230K0FKED" 0402L 199.2,738.85 r270 bottom value=30.0k
R158 "CRCW0402100KFKED" 0402L 65.68,589.85 r90 bottom value=100k
R159 "ERJ-2GE0R00X" 0402L 24.43,589.71 r90 bottom value=0
R160 "ERJ-2GEJ511X" 0402L 7.7,415.91 r0 bottom value=510
R161 "MCT06030Z0000ZP500" 0603 2060,257.5 r90 bottom value=0
R162 "CRCW02010000Z0ED" 0201_Silk 1470.25,172.28 r90 bottom value=0
R163 "CRCW02010000Z0ED" 0201_Silk 1390.25,171.72 r90 bottom value=0
R164 "CRCW02010000Z0ED" 0201_Silk 1352.75,171.72 r90 bottom value=0
R165 "CRCW02010000Z0ED" 0201_Silk 932.75,169.72 r90 bottom value=0
R166 "CRCW02010000Z0ED" 0201_Silk 832.75,169.28 r90 bottom value=0
R167 "CRCW02010000Z0ED" 0201_Silk 799.13,169.28 r90 bottom value=0
R168 "CRCW02010000Z0ED" 0201_Silk 719.63,169.28 r90 bottom value=0
R169 "CRCW02010000Z0ED" 0201_Silk 685.13,169.28 r90 bottom value=0
R170 "CRCW04022K94FKED" 0402 1428.02,163.85 r270 bottom value=2.94k
R171 "CRCW04022K94FKED" 0402 1315.37,163.85 r270 bottom value=2.94k
R172 "CRCW0402100KFKED" 0402L 870.18,161.15 r90 bottom value=100k
R173 "CRCW0402100KFKED" 0402L 759.88,161.15 r90 bottom value=100k
R174 "CRCW040230K0FKED" 0402L 2212.4,-18.11 r90 bottom value=30.0k
R175 "MCT06030Z0000ZP500" 0603 1671,60.5 r90 bottom value=0
R176 "MCT06030Z0000ZP500" 0603 -4,743.5 r270 top value=0
R177 "ERJ-2GE0R00X" 0402L 1209.5,676.57 r270 top value=0
R178 "CRCW040210K0FKED" 0402L 1246.5,806.17 r270 top value=10.0k
R179 "CRCW040210K0FKED" 0402L 1562.35,1009.92 r180 top value=10.0k
R180 "CRCW02010000Z0ED" 0201_Silk 1569.78,1048.33 r0 top value=0
R181 "CRCW02010000Z0ED" 0201_Silk 1732.22,991.17 r0 top value=0
R182 "CRCW02010000Z0ED" 0201_Silk 1684.67,1095.78 r90 top value=0
R183 "ERJ-2GE0R00X" 0402L 1739.65,1026.68 r0 top value=0
R184 "CRCW040210K0FKED" 0402L 140.38,1013.35 r270 top value=10.0k
R185 "CRCW02010000Z0ED" 0201_Silk 257.83,1021.22 r90 top value=0
R186 "CRCW02010000Z0ED" 0201_Silk 271.78,973.33 r0 top value=0
R187 "ERJ-2GE0R00X" 0402L 200.98,913.35 r270 top value=0
R188 "CRCW02010000Z0ED" 0201_Silk 163.83,921.22 r90 top value=0
R189 "ERJ-2GEJ361X" 0402L -14.4,266.73 r90 top value=360
R190 "CRCW04023R83FKED" 0402L 1403.85,1273.74 r90 bottom value=3.83
R191 "CRCW04023R83FKED" 0402L 1734.8,1267.65 r90 bottom value=3.83
R192 "CRCW04023R83FKED" 0402L 1364.9,867.35 r270 bottom value=3.83
R193 "CRCW04023R83FKED" 0402L 1735.6,865.35 r270 bottom value=3.83
R194 "CRCW04024K87FKED" 0402L 677.52,1631.85 r270 bottom value=4.87k
R195 "CRCW040210K0FKED" 0402L 1216.27,1169.81 r0 top value=10.0k
R196 "CRCW040210K0FKED" 0402L 971,1725.91 r270 bottom value=10.0k
R197 "CRCW02010000Z0ED" 0201 2568,1959 r180 top value=0
R198 "CRCW02010000Z0ED" 0201 2568,1922 r180 top value=0
S1 "CHS-01TB" SW_CHS-01TB 760,1230 r90 top locked
SW1 "KMR243GLFG" SW_KMR243GLFG 336.65,1437.52 r180 top
SW2 "KMR243GLFG" SW_KMR243GLFG 335.35,1209.76 r180 top
TP1 "TSW-101-17-T-S" Samtec_TSW-101-17-T-S 195,1840 r0 top
TP2 "TSW-101-17-T-S" Samtec_TSW-101-17-T-S 196.94,1739.77 r0 top
U1 "MX25V1635FZNQ" WSON-8L_6x5MM_EP 1845.23,1980.68 r0 top
U2 "AWR1243FBIGABLQ1" ABL0161A 2294.55,1477.9 r180 top locked
U3 "TCAN1042HGVDQ1" D0008A_L 1117.37,940.26 r270 top
U4 "TPS7A8101QDRBRQ1" DRB0008A 2048.18,912.92 r270 top
U5 "TPS7A8801RTJR" RTJ0020D 1599.35,1728.32 r0 top
U6 "TM4C1294NCPDTT3" PDT0128A 511.79,1248.04 r0 bottom
U7 "LM4040C25QDBZR" DBZ0003A_N 8.08,1177.09 r180 bottom
U8 "LP87524JRNFRQ1" RNF0026C 1551,1080.5 r0 bottom locked
U9 "TPS79601DRBR" DRB0008B 62.83,736.32 r270 bottom
U10 "TPD4E004DRYR" DRY0006A 1976,355.5 r270 top
U11 "TMP112AIDRLR" DRL0006A 1651.46,1024.75 r0 top
U12 "TMP112AIDRLR" DRL0006A 200.81,1001.54 r270 top
U13 "TS3A5018RSVR" RSV0016A 1091.86,1207.21 r270 top
Y1 "CX3225SA40000D0PTWCC" Kyocera_CX3225SA 1978.72,1281.14 r180 top
Y2 "NX3225SA-16.000M-STD-CRS-2" NDK_NX3225SA 978.31,1081.5 r270 bottom
ZZ1 "This Assembly Note is for PCB labels only" AssemblyNoteLabel -484.07,3129.33 r0 top
ZZ2 "These assemblies are ESD sensitive, ESD precautions shall be observed." AssemblyNote -484.07,3020.44 r0 top
ZZ3 "These assemblies must be clean and free from flux and all contaminants. Use of no clean flux is not acceptable." AssemblyNote -484.07,2931.89 r0 top
ZZ4 "These assemblies must comply with workmanship standards IPC-A-610 Class 2, unless otherwise specified." AssemblyNote -484.07,2843.33 r0 top
ZZ5 "Micro USB cable, Brackets, Screws, Nuts, Jumpers and Bump on need to be placed in a plastic bag" AssemblyNote -485.07,2750.33 r0 top

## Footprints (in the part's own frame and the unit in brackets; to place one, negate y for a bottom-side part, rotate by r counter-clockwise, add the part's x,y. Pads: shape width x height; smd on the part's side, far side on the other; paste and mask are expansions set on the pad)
0201 [mm] "Data from Kemet datasheet CC101_COM dated 7/28/11"
  rect 0.46x0.42 smd: 1(-0.33,0) 2(0.33,0)
  body extent -0.31,-0.16 0.31,0.16, height 0.26
0201_033 [mm] "SMD, 2-Leads, Height 0.33mm"
  rect 0.46x0.42 smd: 1(-0.33,0) 2(0.33,0)
  body extent -0.31,-0.16 0.31,0.16, height 0.33
0201_Silk [mm] "Data from Kemet datasheet CC101_COM dated 7/28/11"
  rect 0.46x0.42 smd: 1(-0.33,0) 2(0.33,0)
  silkscreen extent -0.75,-0.4 0.75,0.4, body extent -0.31,-0.16 0.31,0.16, height 0.26
0402 [mm] "0402 from SM-752 data"
  rect 0.8x0.6 smd: 1(-0.6,0) 2(0.6,0)
  silkscreen extent -1.22,-0.52 1.22,0.52, body extent -0.55,-0.3 0.55,0.3, height 0.6
0402_065L [mm] "0402"
  rect 0.6x0.5 smd: 1(-0.5,0) 2(0.5,0)
  body extent -0.55,-0.3 0.55,0.3, height 0.65
0402L [mm] "0402 from SM-752 data"
  rect 0.6x0.5 smd: 1(-0.5,0) 2(0.5,0)
  body extent -0.55,-0.3 0.55,0.3, height 0.6
0603 [mm] "0603 from SM-752 data"
  rect 1x0.95 smd: 1(-0.8,0) 2(0.8,0)
  silkscreen extent -1.52,-0.69 1.52,0.69, body extent -0.87,-0.47 0.87,0.47, height 1
0805 [mm] "0805 from SM-752 data"
  rect 1.3x1.5 smd: 1(-0.85,0) 2(0.85,0)
  silkscreen extent -1.72,-0.97 1.72,0.97, body extent -1.1,-0.72 1.1,0.72, height 1.45
0805_HV [mil] "0805 with 30mil clearance between pads"
  rect 50x63 smd: 1(-40,0) 2(40,0)
  silkscreen extent -74,-40 74,40, body extent -43,-29 43,29, height 57
0805_HV1 [mm] "Custom footprint based on analyzing multiple manufacturer recommendations"
  rrect10% 1x1.25 smd: 1(-1,0) 2(1,0)
  silkscreen extent -0.2,-0.75 0.2,0.75, body extent -1.1,-0.72 1.1,0.73, height 1.45
1206 [mm] "1206 from SM-752 data"
  rect 1.3x1.85 smd: 1(-1.45,0) 2(1.45,0)
  silkscreen extent -2.4,-1.21 2.4,1.21, body extent -1.7,-0.9 1.7,0.9, height 1.35
1206_180 [mm] "1206_180"
  rect 1.1x1.6 smd: 1(-1.7,0) 2(1.7,0)
  silkscreen extent -0.9,-1 0.9,1, body extent -1.75,-0.95 1.75,0.95, height 1.8
2010 [mm] "Chip Capacitor, Body 5.08x2.54mm, IPC Medium Density"
  rect 1.6x2.7 smd: 1(-2.3,0) 2(2.3,0)
  silkscreen extent -3.42,-1.65 3.42,1.65, body extent -2.73,-1.45 2.73,1.45, height 1.66
2010L [mm]
  rect 1.2x2.7 smd: 1(-2.2,0) 2(2.2,0)
  silkscreen extent -1.2,-1.25 1.2,1.25, body extent -2.73,-1.45 2.73,1.45, height 1.66
3528-21 [mm] "Medium Density IPC, based on Kemet datasheet 2016-10-20"
  rrect6% 1.8x2.23 smd: 1(-1.46,0) 2(1.46,0)
  silkscreen extent -2.29,-1.5 0.76,1.5, body extent -1.85,-1.5 1.85,1.5, height 2.12
ABL0161A [mm] "BGA, 161-Balls, Body 10.4x10.4mm, Pitch 0.65mm"
  round 0.32 smd mask+0.05: A1(-4.55,4.55) A2(-3.9,4.55) A3(-3.25,4.55) A5(-1.95,4.55) A7(-0.65,4.55) A9(0.65,4.55) A10(1.3,4.55) A13(3.25,4.55) A14(3.9,4.55) A15(4.55,4.55) B1(-4.55,3.9) B2(-3.9,3.9) B3(-3.25,3.9) B4(-2.6,3.9) B5(-1.95,3.9) B6(-1.3,3.9) B7(-0.65,3.9) B8(0,3.9) B9(0.65,3.9) B10(1.3,3.9) B11(1.95,3.9) B12(2.6,3.9) B13(3.25,3.9) B14(3.9,3.9) B15(4.55,3.9) C1(-4.55,3.25) C2(-3.9,3.25) C3(-3.25,3.25) C4(-2.6,3.25) C5(-1.95,3.25) C6(-1.3,3.25) C7(-0.65,3.25) C8(0,3.25) C9(0.65,3.25) C13(3.25,3.25) C14(3.9,3.25) C15(4.55,3.25) D1(-4.55,2.6) D2(-3.9,2.6) D13(3.25,2.6) D15(4.55,2.6) E1(-4.55,1.95) E2(-3.9,1.95) E3(-3.25,1.95) E5(-1.95,1.95) E6(-1.3,1.95) E8(0,1.95) E10(1.3,1.95) E11(1.95,1.95) E13(3.25,1.95) E14(3.9,1.95) E15(4.55,1.95) F2(-3.9,1.3) F3(-3.25,1.3) F5(-1.95,1.3) F9(0.65,1.3) F11(1.95,1.3) F13(3.25,1.3) F14(3.9,1.3) G1(-4.55,0.65) G2(-3.9,0.65) G3(-3.25,0.65) G5(-1.95,0.65) G6(-1.3,0.65) G7(-0.65,0.65) G8(0,0.65) G10(1.3,0.65) G13(3.25,0.65) G14(3.9,0.65) G15(4.55,0.65) H2(-3.9,0) H3(-3.25,0) H5(-1.95,0) H7(-0.65,0) H9(0.65,0) H11(1.95,0) H13(3.25,0) H14(3.9,0) H15(4.55,0) J1(-4.55,-0.65) J2(-3.9,-0.65) J3(-3.25,-0.65) J5(-1.95,-0.65) J6(-1.3,-0.65) J7(-0.65,-0.65) J8(0,-0.65) J10(1.3,-0.65) J13(3.25,-0.65) J14(3.9,-0.65) J15(4.55,-0.65) K2(-3.9,-1.3) K3(-3.25,-1.3) K5(-1.95,-1.3) K7(-0.65,-1.3) K8(0,-1.3) K9(0.65,-1.3) K10(1.3,-1.3) K11(1.95,-1.3) K13(3.25,-1.3) K14(3.9,-1.3) K15(4.55,-1.3) L1(-4.55,-1.95) L2(-3.9,-1.95) L3(-3.25,-1.95) L5(-1.95,-1.95) L6(-1.3,-1.95) L8(0,-1.95) L10(1.3,-1.95) L13(3.25,-1.95) L14(3.9,-1.95) L15(4.55,-1.95) M2(-3.9,-2.6) M3(-3.25,-2.6) M13(3.25,-2.6) M14(3.9,-2.6) M15(4.55,-2.6) N1(-4.55,-3.25) N2(-3.9,-3.25) N3(-3.25,-3.25) N4(-2.6,-3.25) N5(-1.95,-3.25) N6(-1.3,-3.25) N7(-0.65,-3.25) N8(0,-3.25) N9(0.65,-3.25) N10(1.3,-3.25) N11(1.95,-3.25) N12(2.6,-3.25) N13(3.25,-3.25) N14(3.9,-3.25) N15(4.55,-3.25) P1(-4.55,-3.9) P2(-3.9,-3.9) P3(-3.25,-3.9) P4(-2.6,-3.9) P5(-1.95,-3.9) P6(-1.3,-3.9) P7(-0.65,-3.9) P8(0,-3.9) P9(0.65,-3.9) P10(1.3,-3.9) P11(1.95,-3.9) P12(2.6,-3.9) P13(3.25,-3.9) P14(3.9,-3.9) P15(4.55,-3.9) R1(-4.55,-4.55) R2(-3.9,-4.55) R3(-3.25,-4.55) R4(-2.6,-4.55) R5(-1.95,-4.55) R6(-1.3,-4.55) R7(-0.65,-4.55) R8(0,-4.55) R9(0.65,-4.55) R10(1.3,-4.55) R11(1.95,-4.55) R12(2.6,-4.55) R13(3.25,-4.55) R14(3.9,-4.55) R15(4.55,-4.55)
  silkscreen extent -5.3,-5.3 5.3,5.3, body extent -5.2,-5.2 5.2,5.2, height 0.62
AssemblyNote [mil] "Assembly Note"
AssemblyNoteLabel [mil] "Assembly Note for PCB Labels"
CE_Mark_5mm [mil] "Minimum text height for CE Mark"
  silkscreen extent -138,-98 138,98
CONN_105017-0001 [mm] "Molex Micro USB-B"
  rect 0.4x1.35 smd: 1(-1.3,1.35) 2(-0.65,1.35) 3(0,1.35) 4(0.65,1.35) 5(1.3,1.35)
  oval 1.2x1.9 hole 0.6 slot 1.3 at 90 deg: 6(-3.5,-1.35) 9(3.5,-1.35)
  rect 1.5x1.9 smd: 7(-1,-1.35) 8(1,-1.35)
  round 1.45 hole 0.85: 10(2.5,1.35) 11(-2.5,1.35)
  TOP region: 3.5,-2.3 2.3,-2.3 2.3,-0.4 3.5,-0.4
  TOP region: -3.5,-0.4 -2.3,-0.4 -2.3,-2.3 -3.5,-2.3
  silkscreen extent -4.1,-0.2 4.1,1.4, body extent -4.1,-3.93 4.1,1.5, height 2.72
CUI_PJ-002AH [mm] "DC POWER JACK, R/A, TH"
  rrect50% 1.5x5.25 hole 1 slot 3.5 at 90 deg: 1(-3,0)
  oval 1.5x4.5 hole 1 slot 3 at 90 deg: 2(3,0)
  oval 4.5x1.5 hole 1 slot 3 at 0 deg: 3(0,4.7)
  silkscreen extent -4.1,-4.5 10.7,4.5, body extent -3.7,-4.5 10.7,4.9, height 11
D0008A_L [mm] "SOIC, 8-Leads, Body 4.9x3.9mm, Pitch 1.27mm, IPC High Density"
  oval 1.25x0.55 smd: 1(-2.625,1.905) 2(-2.625,0.635) 3(-2.625,-0.635) 4(-2.625,-1.905) 5(2.625,-1.905) 6(2.625,-0.635) 7(2.625,0.635) 8(2.625,1.905)
  silkscreen extent -3.1,-2.5 0.9,2.5, body extent -3,-2.45 3,2.45, height 1.63
DBZ0003A_N [mm] "SOT23, 3-Leads, Body 2.9x1.3mm, Pitch 0.95mm, Lead Span 2.4mm, IPC Medium Density"
  rrect17% 1x0.6 smd: 1(-1.2,0.95) 2(-1.2,-0.95) 3(1.2,0)
  silkscreen extent 0.2,-1.5 0.7,1.5, body extent -1.26,-1.46 1.26,1.46, height 0.98
DFE252012P [mm] "TOKO, Pad sizes increased as per request"
  rect 0.9x2 smd: 1(-1.05,0) 2(1.05,0)
  silkscreen extent -0.3,-1.2 0.3,1.2, body extent -1.35,-1.1 1.35,1.1, height 1.2
DRB0008A [mm] "SON, 8-Leads, Body 3x3mm, Pitch 0.65mm, Thermal Pad 1.75x1.5mm, TI Recommended"
  rrect33% 0.6x0.3 smd: 1(-1.4,0.975) 2(-1.4,0.325) 3(-1.4,-0.325) 4(-1.4,-0.975) 5(1.4,-0.975) 6(1.4,-0.325) 7(1.4,0.325) 8(1.4,0.975)
  rrect7% 1.5x1.75 smd paste-0.75: 9(0,0)
  TOP region: -0.465,-1.5 -0.465,-0.875 -0.75,-0.875 -0.75,0.875 -0.465,0.875 -0.465,1.5 -0.185,1.5 -0.185,0.875 0.185,0.875 0.185,1.5 0.465,1.5 0.465,0.875 0.75,0.875 0.75,-0.875 0.465,-0.875 0.465,-1.5 0.185,-1.5 0.185,-0.875 -0.185,-0.875 -0.185,-1.5
  silkscreen extent -1.73,-1.73 1.73,1.73, body extent -1.58,-1.57 1.57,1.58, height 1.01
DRB0008B [mm] "SON, 8-Leads, Body 3x3mm, Pitch 0.65mm, Thermal Pad 2.4x1.65mm, TI Recommended"
  rrect33% 0.6x0.3 smd: 1(-1.4,0.975) 2(-1.4,0.325) 3(-1.4,-0.325) 4(-1.4,-0.975) 5(1.4,-0.975) 6(1.4,-0.325) 7(1.4,0.325) 8(1.4,0.975)
  rrect9% 1.47x1.06 on Bottom Paste: 9(0,-0.63) 9(0,0.63)
  rrect6% 1.65x2.4 smd paste-1.2: 9(0,0)
  silkscreen extent -1.73,-1.73 1.73,1.73, body extent -1.5,-1.5 1.5,1.5, height 0.96
DRL0006A [mm] "SOTFL, 6-Flat Leads, Body 1.2x1.6x0.6mm, Pitch 0.5mm, TI recommended"
  rrect33% 0.67x0.3 smd: 1(-0.74,0.5) 2(-0.74,0) 3(-0.74,-0.5) 4(0.74,-0.5) 5(0.74,0) 6(0.74,0.5)
  silkscreen extent -0.9,-0.95 0.5,0.95, body extent -0.8,-0.8 0.8,0.8, height 0.61
DRY0006A [mm] "PSON, 6-Leads, Body 1x1.45mm, Pitch 0.5mm, TI Recommended"
  rrect50% 0.35x0.2 smd: 1(-0.275,0.5)
  rrect50% 0.3x0.2 smd: 2(-0.3,0) 3(-0.3,-0.5) 4(0.3,-0.5) 5(0.3,0) 6(0.3,0.5)
  body extent -0.5,-0.72 0.5,0.73, height 0.58
ESD_Overlay_Small [mil]
  silkscreen extent -62,-48 64,61
FCC_disclaimer [mil]
Fiducial10-20 [mm]
  round 1 smd mask+0.5: 1(0,0)
  TOP keep-out circle w1.178: c0,0 r0.5
IEC_HotSurface_Small [mil]
  silkscreen extent -107,-93 107,92
Johnson_128-0711-201 [mm] "UMC Straight Jack Receptacle, 50 Ohm, SMT"
  rrect10% 1x1.05 smd: 1(0,1.525)
  rrect10% 1.05x2.2 smd: 2(-1.475,0) 3(1.475,0)
  silkscreen extent -0.6,-1.3 0.6,-1.3, body extent -1.5,-1.55 1.5,1.55, height 1.25
Kyocera_CX3225SA [mm] "SMD, 4-Leads, Body 3.2x2.5mm"
  rrect10% 1.05x1.45 smd: 1(-0.925,1.075) 2(-0.925,-1.075) 3(0.925,-1.075) 4(0.925,1.075)
  silkscreen extent -1.86,1.09 -1.74,1.21, body extent -1.3,-1.65 1.3,1.65, height 0.9
Label_650x200 [mil] "Thermal Transfer Label"
  round 1 on Mech13: 0(0,0)
  silkscreen extent -325,-100 325,100, body extent -325,-100 325,100, height 1
NDK_NX3225SA [mm] "NDK"
  rect 1.2x1.4 smd: 1(-0.8,1.1) 2(-0.8,-1.1) 3(0.8,-1.1) 4(0.8,1.1)
  body extent -1.3,-1.65 1.3,1.65, height 0.7
NLCV32 [mm] "TDK"
  rect 1.2x2 smd: 1(-1.6,0) 2(1.6,0)
  silkscreen extent -0.9,-1.4 0.9,1.4, body extent -1.7,-1.35 1.7,1.35, height 2.4
On-Shore_OSTTE030161 [mm] "Terminal Block, 3.5mm, 3x1, TH"
  rrect50% 1.7x1.7 hole 1.2: 1(-3.5,0)
  round 1.7 hole 1.2: 2(0,0) 3(3.5,0)
  silkscreen extent -5.25,-3.6 5.25,4.05, body extent -5.75,-3.6 5.75,3.4, height 8.4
